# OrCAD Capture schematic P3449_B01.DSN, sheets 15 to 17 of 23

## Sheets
15 0008_USB3.1 x4 HUB: size Custom
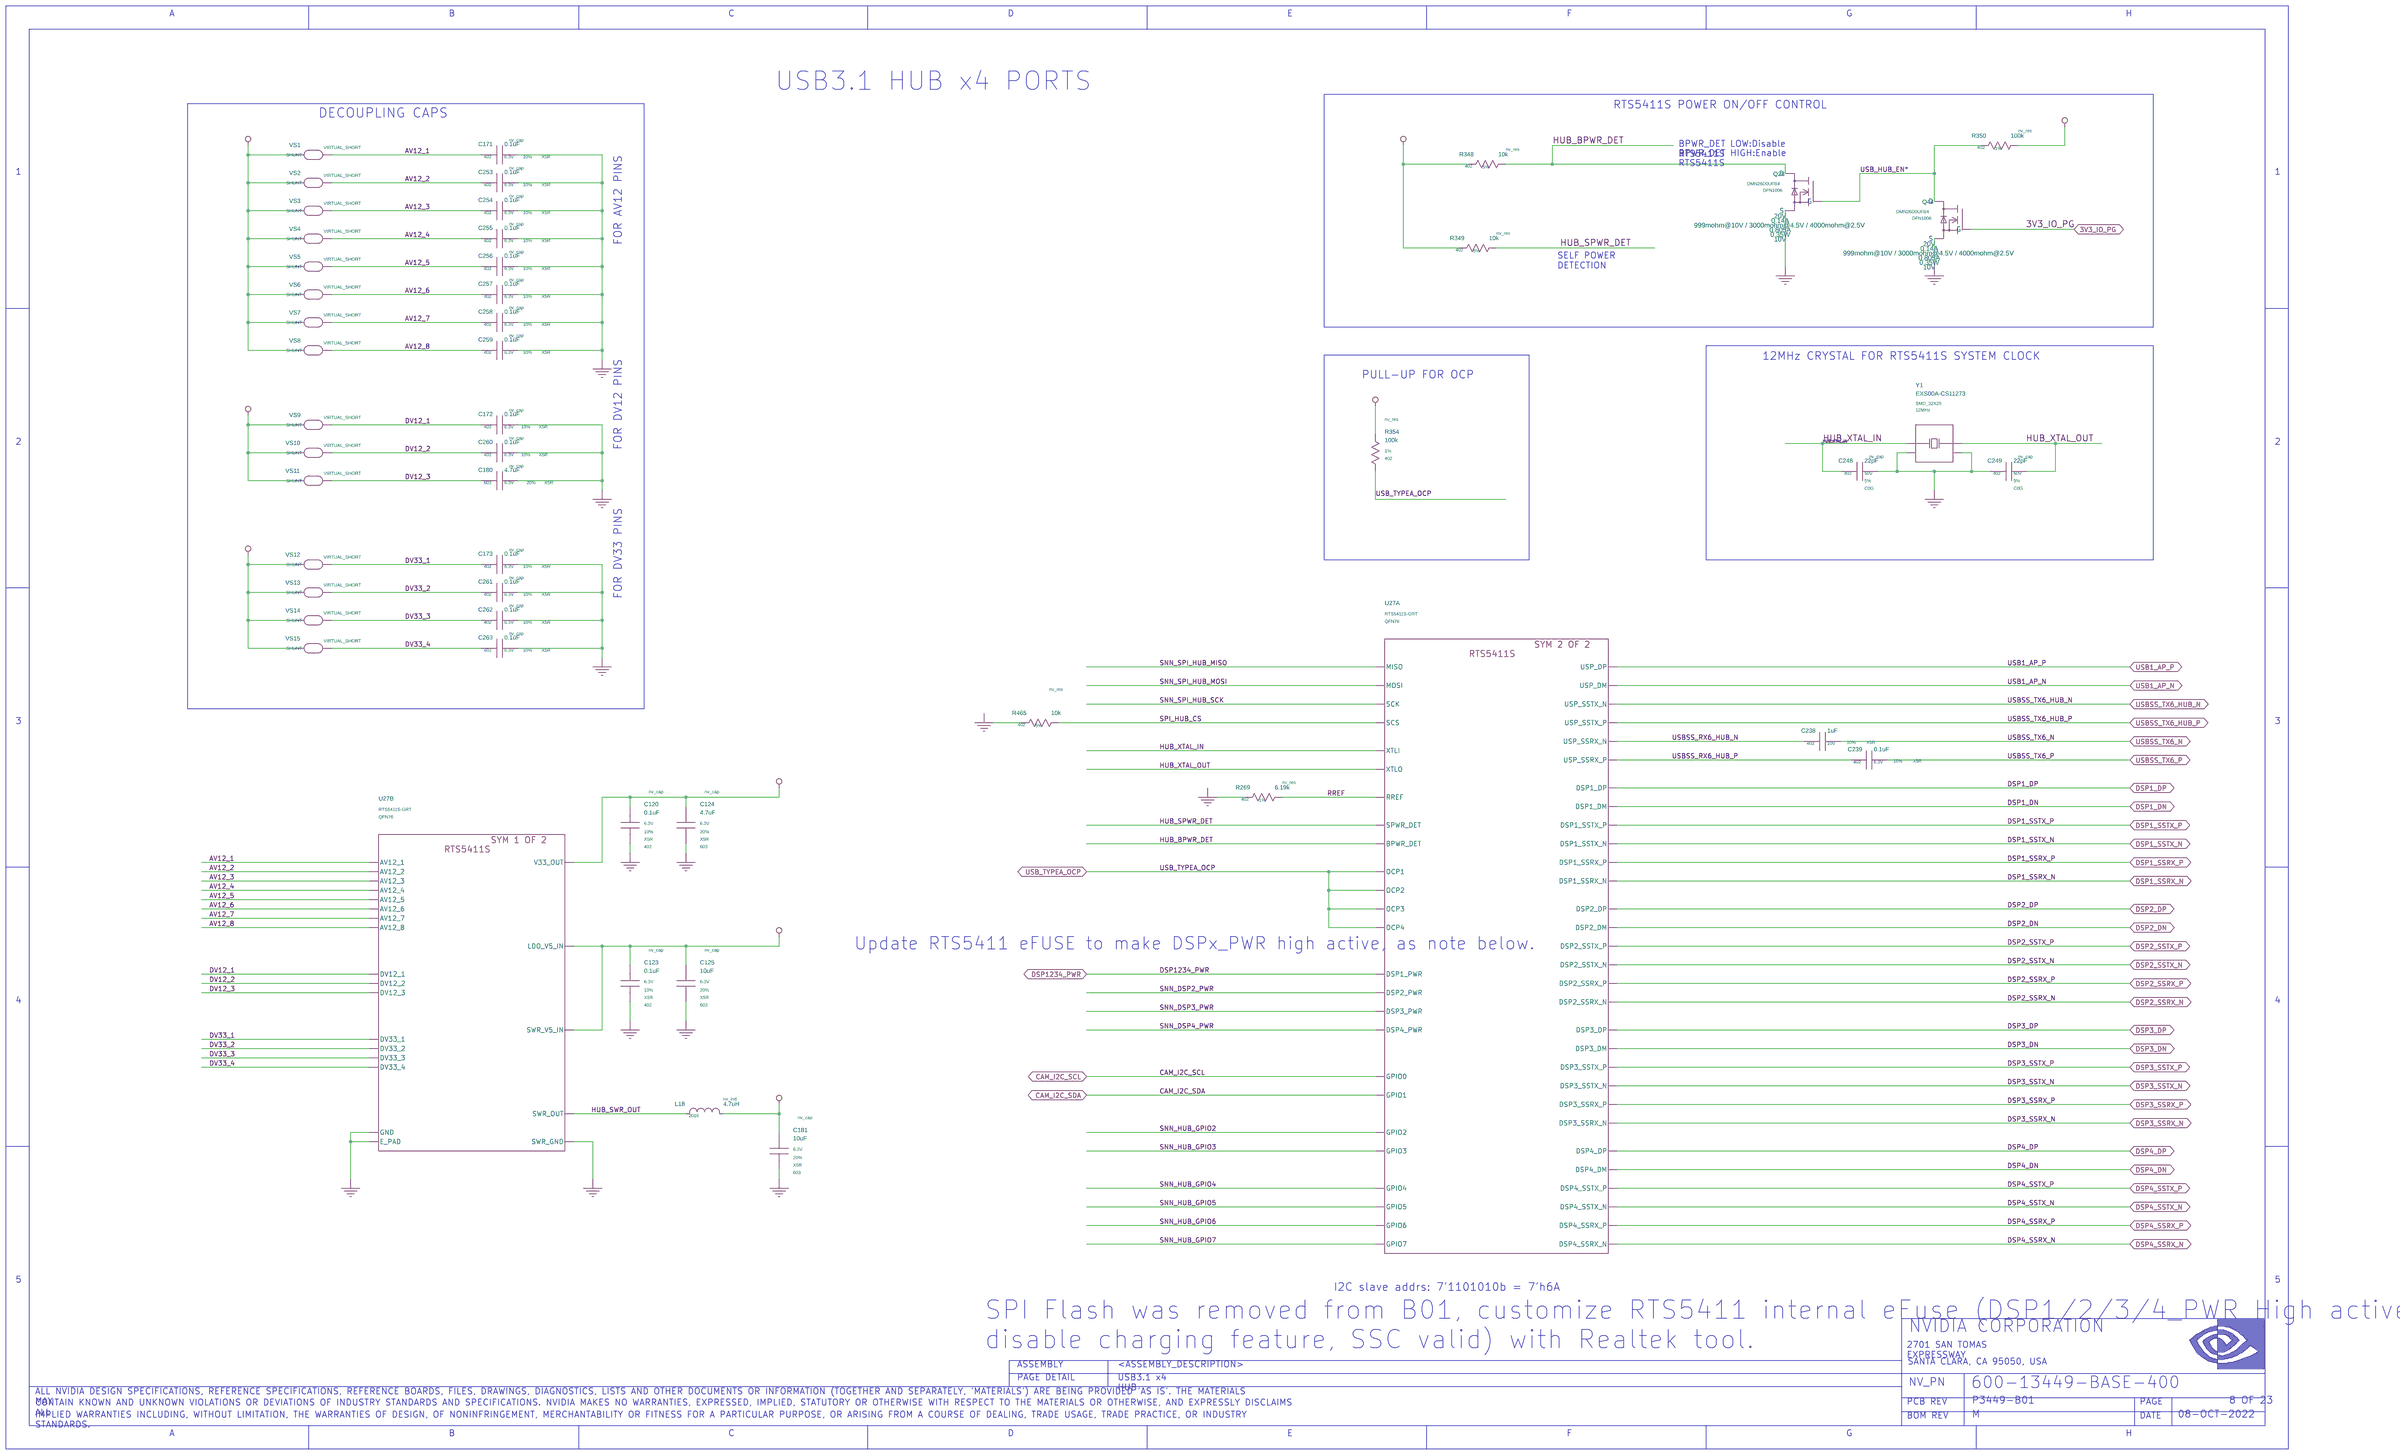
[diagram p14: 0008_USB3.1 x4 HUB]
16 0007_USB2.0 micro: size Custom
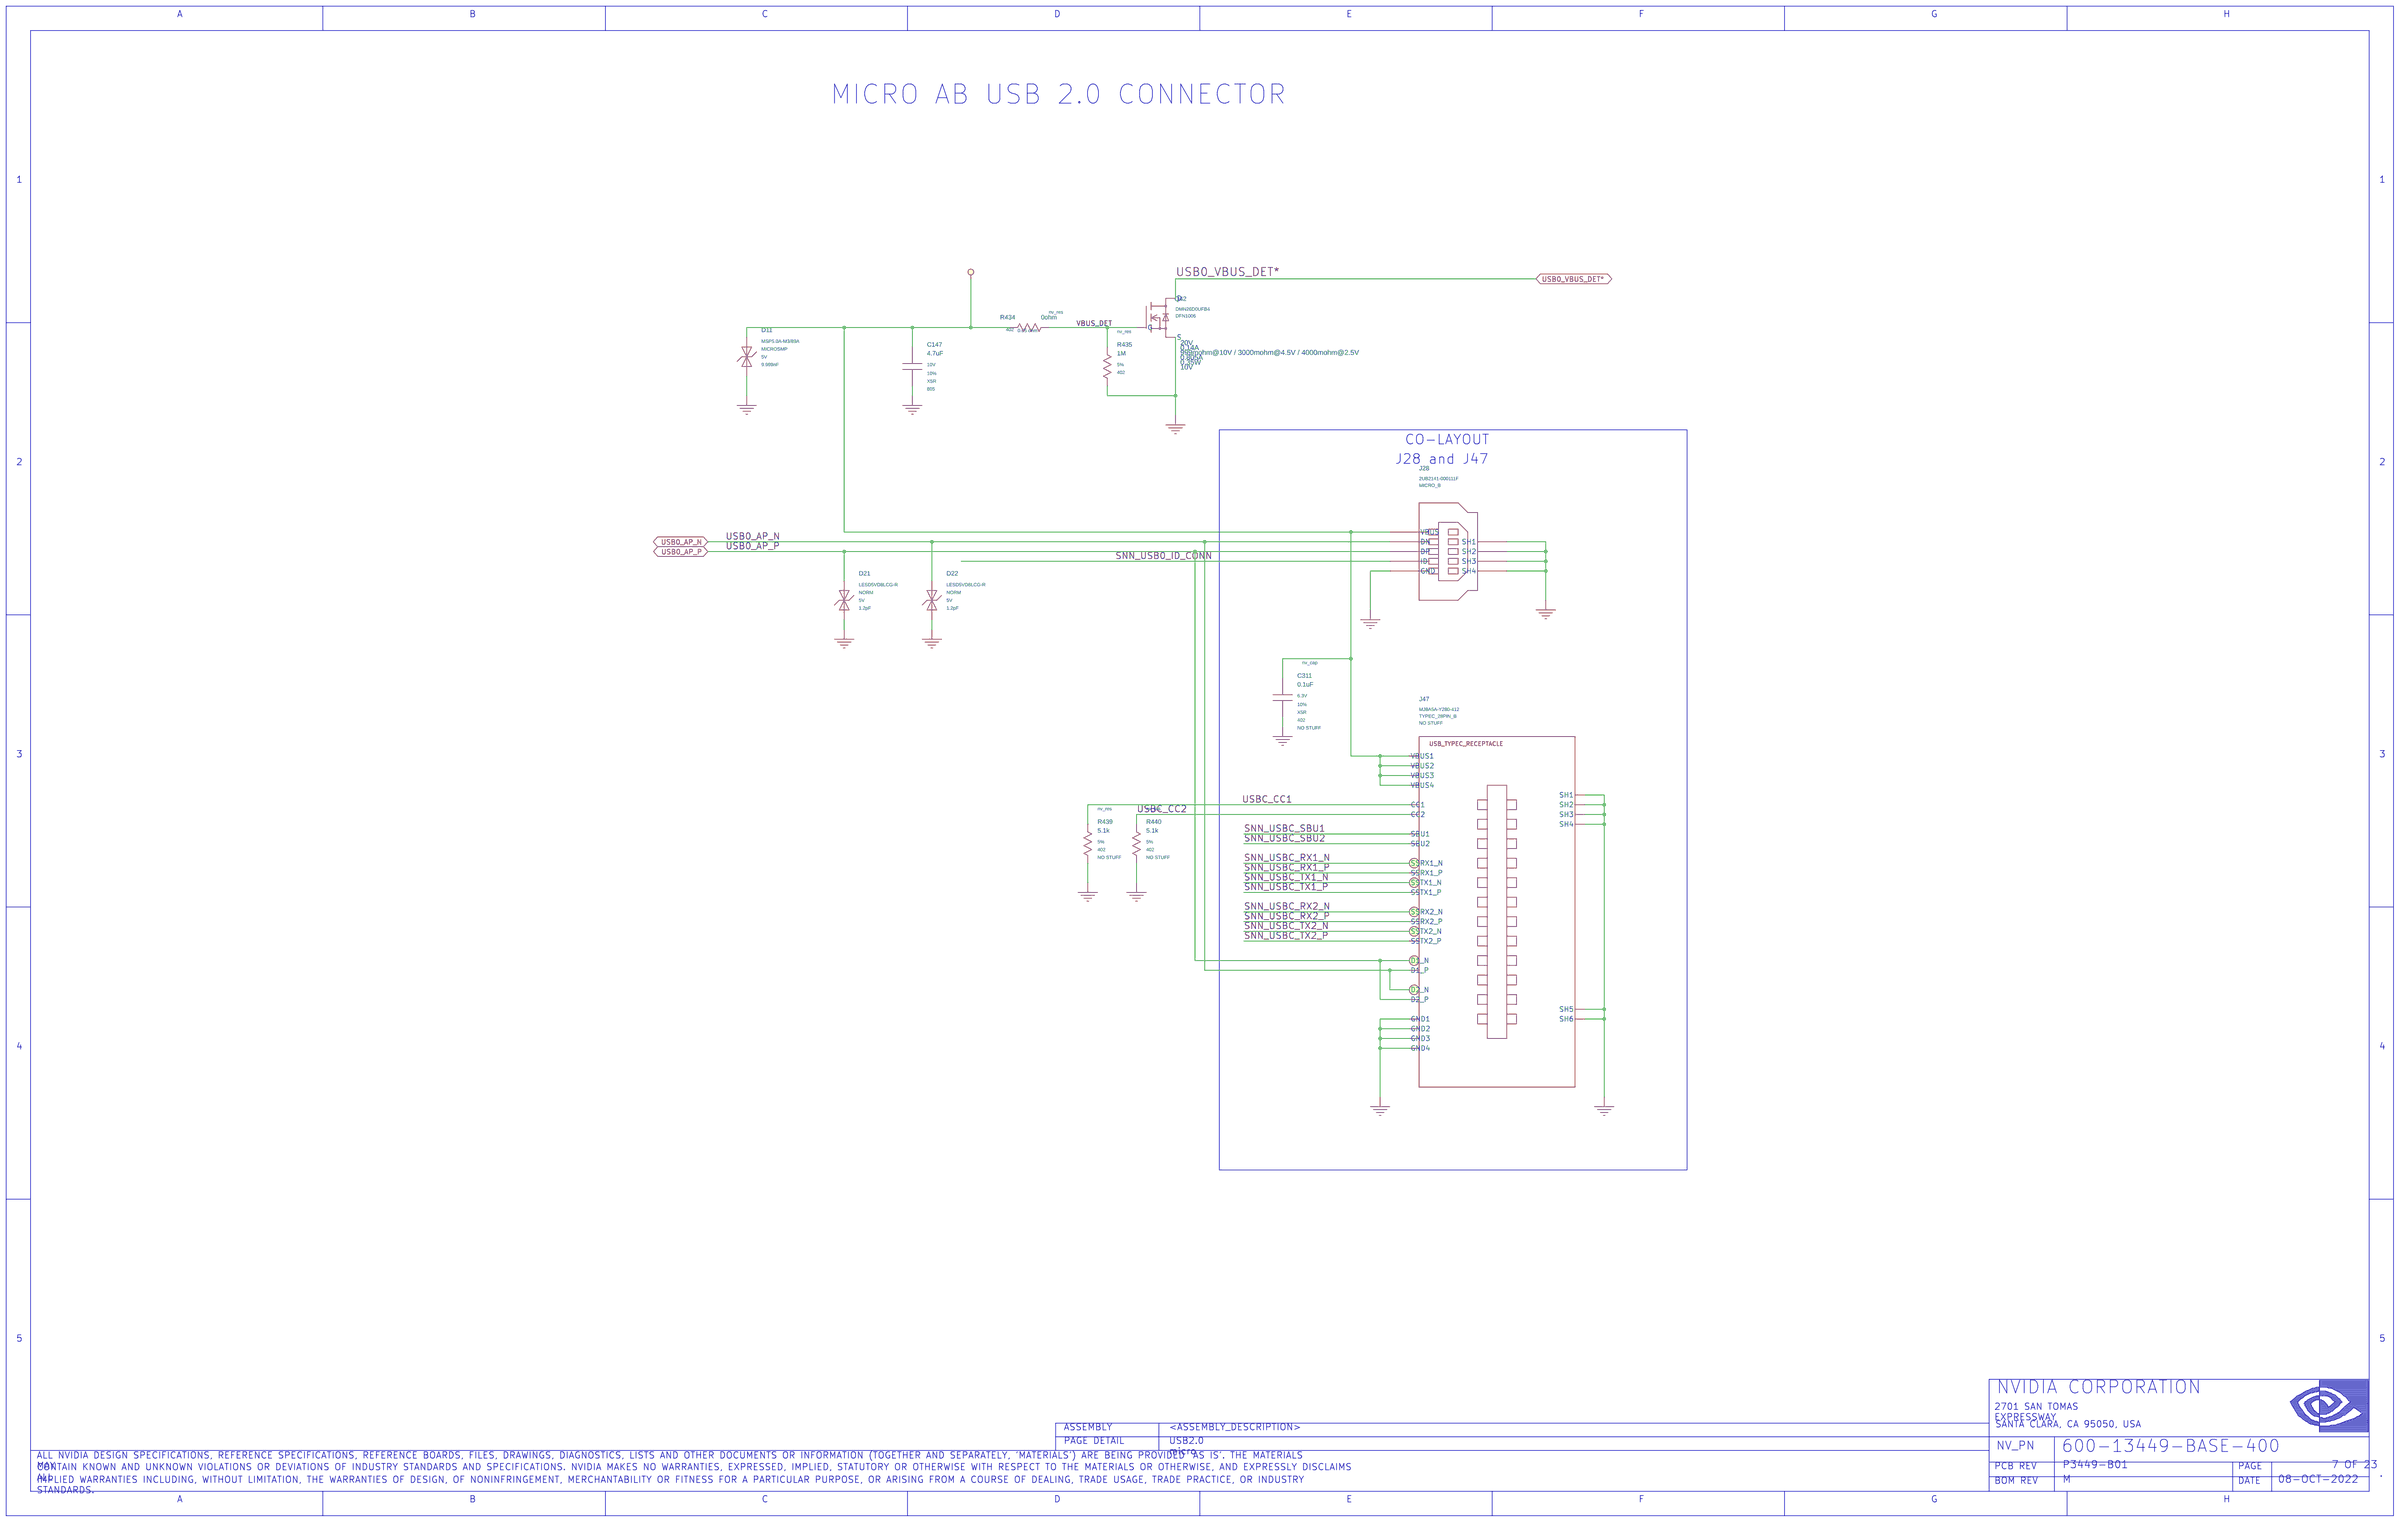
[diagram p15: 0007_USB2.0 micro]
17 0006_SODIMM connector 3_3: size Custom
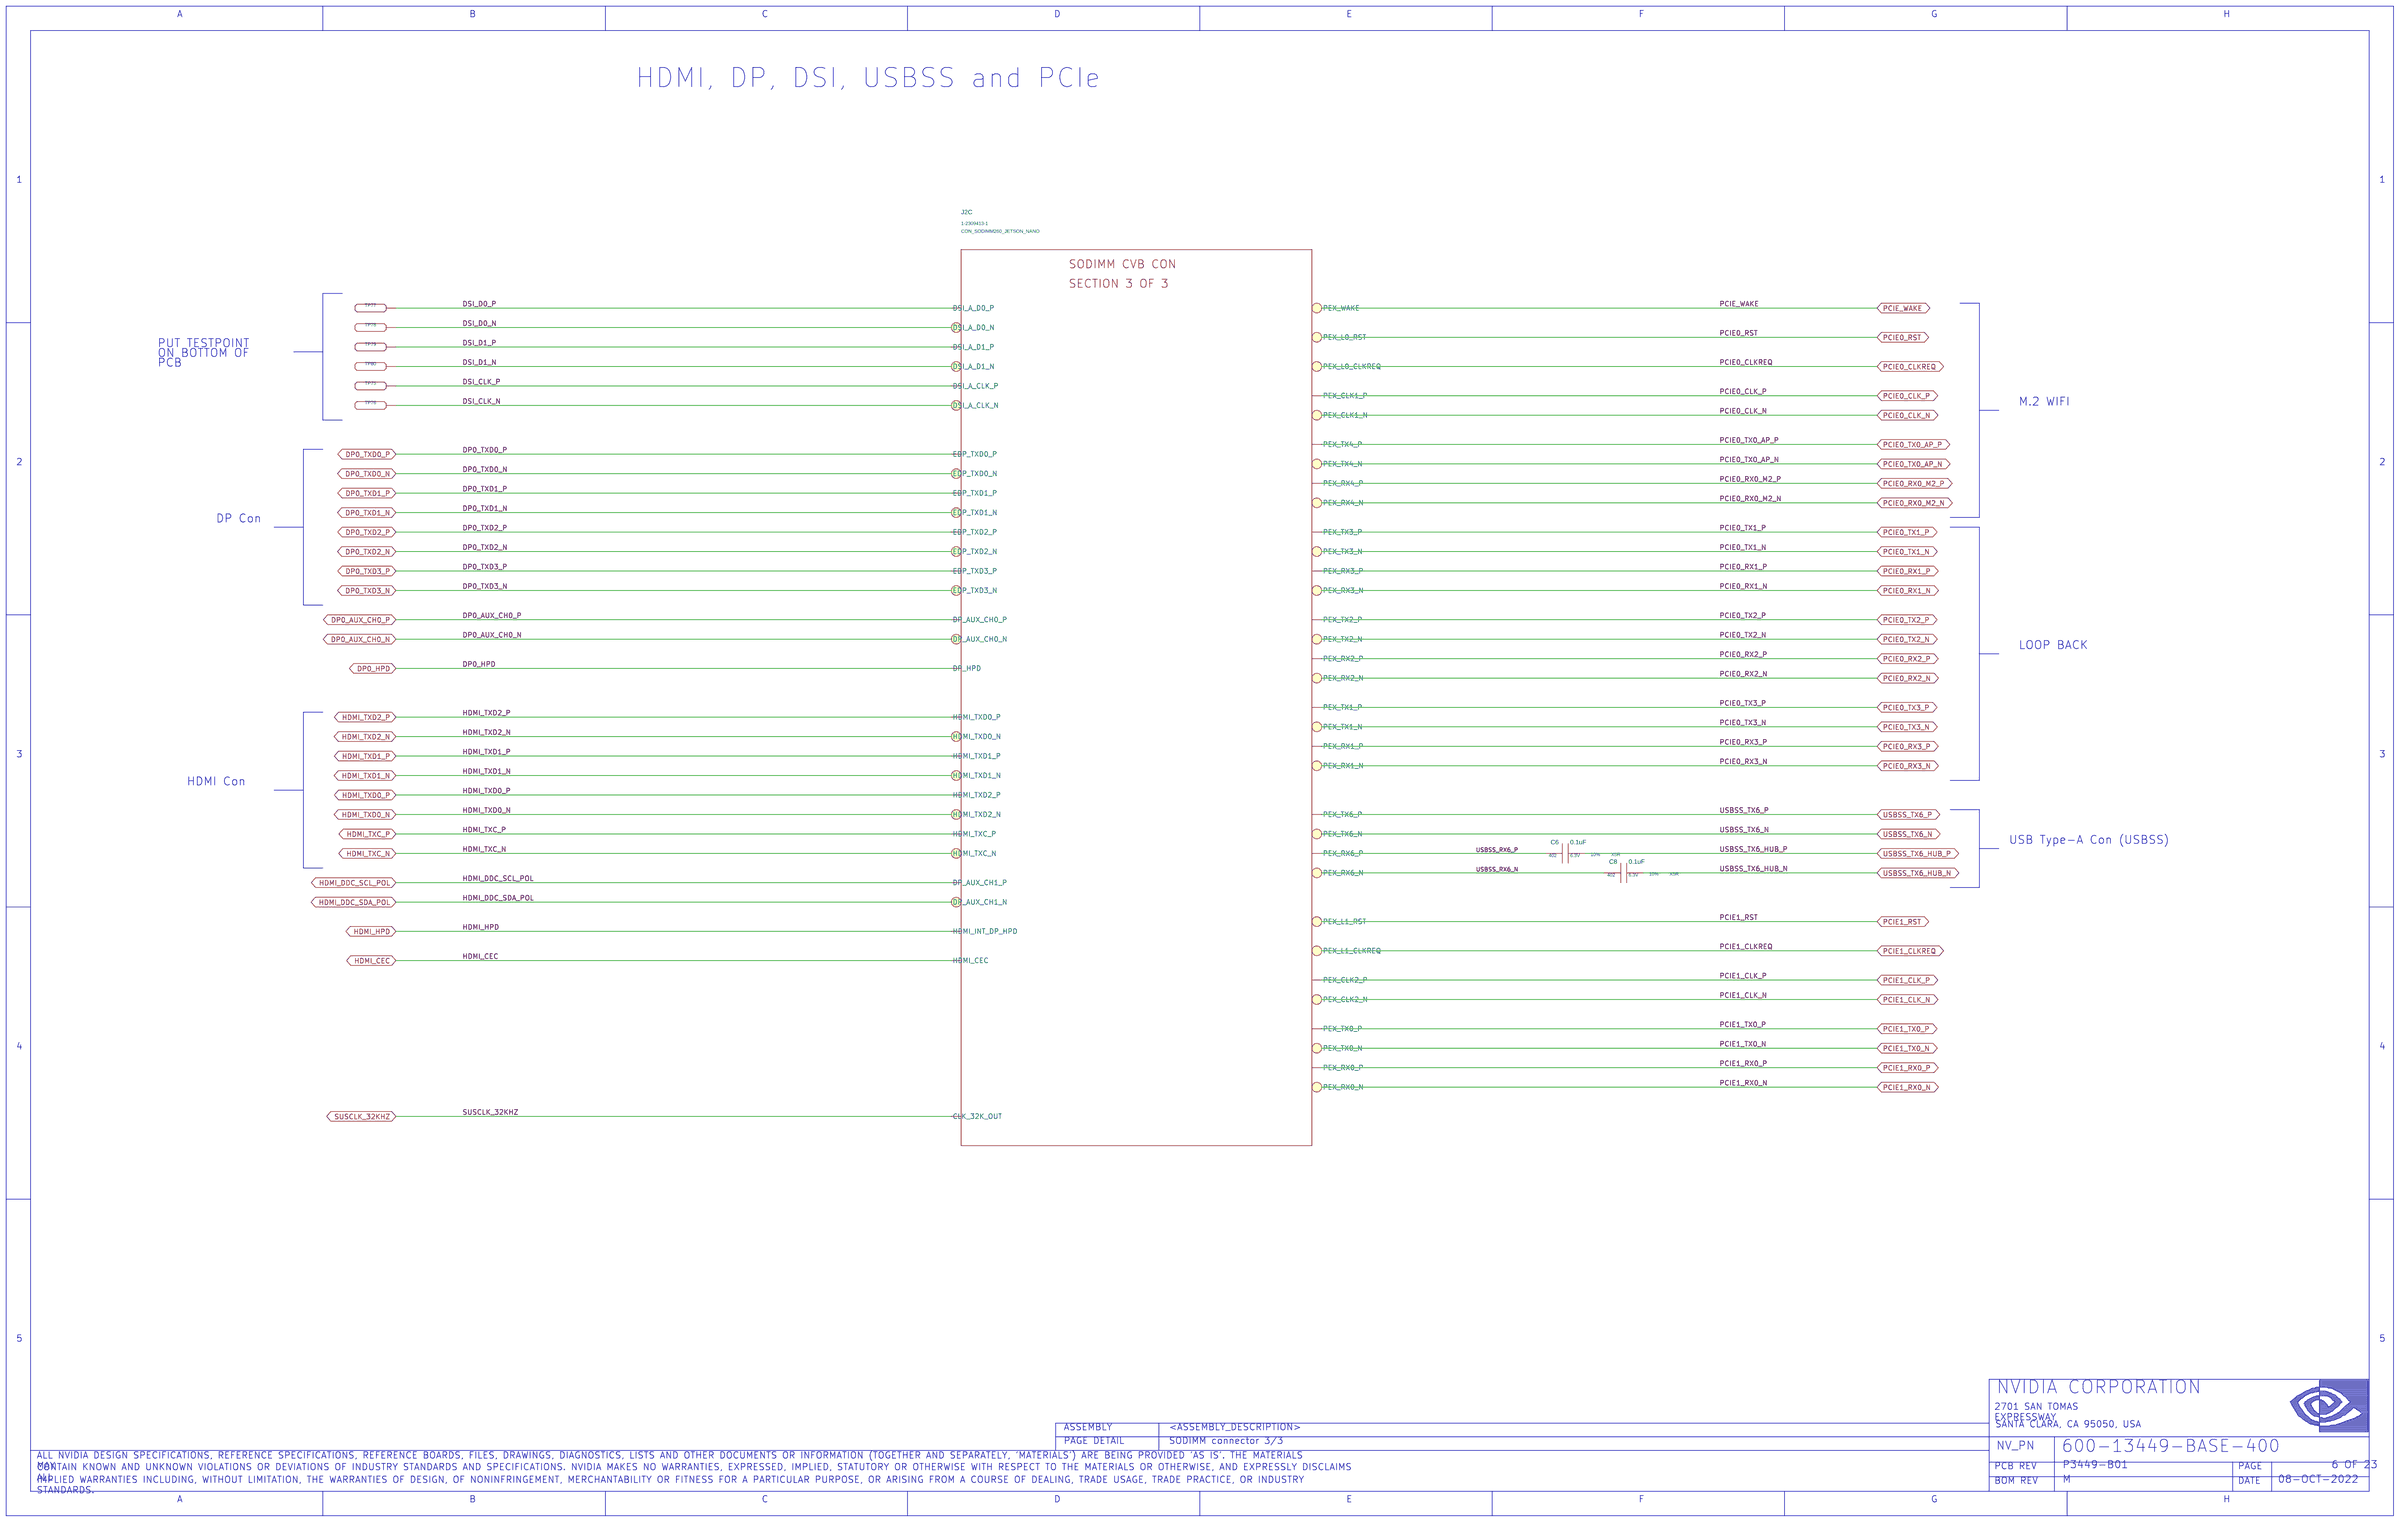
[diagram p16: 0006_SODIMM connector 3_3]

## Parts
sheet 0005_SODIMM connector 2_3
J2  CON_SODIMM_260  [CON_SODIMM_260_SMT_RA_F_P005]  (sections A,B,C)
sheet 0006_SODIMM connector 3_3
C6  0.1uF  [402]
C8  0.1uF  [402]
TP75  LABTESTPOINT  [LTPB071C125D045C025P]
TP76  LABTESTPOINT  [LTPB071C125D045C025P]
TP77  LABTESTPOINT  [LTPB071C125D045C025P]
TP78  LABTESTPOINT  [LTPB071C125D045C025P]
TP79  LABTESTPOINT  [LTPB071C125D045C025P]
TP80  LABTESTPOINT  [LTPB071C125D045C025P]
sheet 0007_USB2.0 micro
C147  4.7uF  [805]
C311  0.1uF  [402]
D11  D_ESD  [DIODE_SMD_025X013]
D21  D_ESD  [DIODE_SMD_010X060]
D22  D_ESD  [DIODE_SMD_010X060]
J28  CON_USB  [CON_USB_005_SMT_RA_080X066]
J47  CON_USB3  [CON_USB_024_SMT_RA_F_089X108]
Q42  Q_FET_N_ENH  [DFET_003_SMD_010X006_B]
R434  0ohm  [402]
R435  1M  [402]
R439  5.1k  [402]
R440  5.1k  [402]
sheet 0008_USB3.1 x4 HUB
C120  0.1uF  [402]
C123  0.1uF  [402]
C124  4.7uF  [603]
C125  10uF  [603]
C171  0.1uF  [402]
C172  0.1uF  [402]
C173  0.1uF  [402]
C180  4.7uF  [603]
C181  10uF  [603]
C238  1uF  [402]
C239  0.1uF  [402]
C248  22pF  [402]
C249  22pF  [402]
C253  0.1uF  [402]
C254  0.1uF  [402]
C255  0.1uF  [402]
C256  0.1uF  [402]
C257  0.1uF  [402]
C258  0.1uF  [402]
C259  0.1uF  [402]
C260  0.1uF  [402]
C261  0.1uF  [402]
C262  0.1uF  [402]
C263  0.1uF  [402]
L18  4.7uH  [2016MM]
Q28  Q_FET_N_ENH  [DFET_003_SMD_010X006_B]
Q44  Q_FET_N_ENH  [DFET_003_SMD_010X006_B]
R269  6.19k  [402]
R348  10k  [402]
R349  10k  [402]
R350  100k  [402]
R354  100k  [402]
R465  10k  [402]
U27  U_USB_HUB_RTS5411S  [QFN076Q_P040_0090_T054X054]  (sections A,B)
VS1  VIRTUAL_SHORT  [VIRTUAL_SHORT]
VS2  VIRTUAL_SHORT  [VIRTUAL_SHORT]
VS3  VIRTUAL_SHORT  [VIRTUAL_SHORT]
VS4  VIRTUAL_SHORT  [VIRTUAL_SHORT]
VS5  VIRTUAL_SHORT  [VIRTUAL_SHORT]
VS6  VIRTUAL_SHORT  [VIRTUAL_SHORT]
VS7  VIRTUAL_SHORT  [VIRTUAL_SHORT]
VS8  VIRTUAL_SHORT  [VIRTUAL_SHORT]
VS9  VIRTUAL_SHORT  [VIRTUAL_SHORT]
VS10  VIRTUAL_SHORT  [VIRTUAL_SHORT]
VS11  VIRTUAL_SHORT  [VIRTUAL_SHORT]
VS12  VIRTUAL_SHORT  [VIRTUAL_SHORT]
VS13  VIRTUAL_SHORT  [VIRTUAL_SHORT]
VS14  VIRTUAL_SHORT  [VIRTUAL_SHORT]
VS15  VIRTUAL_SHORT  [VIRTUAL_SHORT]
Y1  12MHz  [XTAL_SMD_4_032X025]

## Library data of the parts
J2 = CON_SODIMM_260: ANGLE: 90; ASSEMBLY: CVB_CONN; CDS_LIB: p3449_b01_lib; CDS_PART_NAME: CON_SODIMM_260_CON_SODIMM260_JETSON_NANO-2309413-1,FEMALE,0.5MM,90,[ ],[ ],YES,NO,NO,25 V,0.5 A,080-1656-000; CDS_PHYS_PART_NAME: CON_SODIMM_260_CON_SODIMM260_JETSON_NANO-2309413-1,FEMALE,0.5MM,90,[ ],[ ],YES,NO,NO,25 V,0.5 A,080-1656-000-080-1656-000; CDS_SEC: 1; CaptureCellPackProp: CON_SODIMM_260A; DEVICE_TYPENAME: CON_SODIMM_260_CON_SODIMM260_JETSON_NANO-2309413-1FEMALE05MM90YESNONO25V05A080-1656-000-080-1656-000; DRAWING: @P3449_B01_LIB.P3449_B01(SCH_1):PAGE4; EMI_GROUND_TAB: NO; GENDER: FEMALE; LATCHING: YES; MAX_CURRENT: 0.5 A; MAX_VOLTAGE: 25 V; NV_NAME: 1-2309413-1; NV_PN: 080-1656-000; PACK_TYPE: CON_SODIMM260_JETSON_NANO; PATH: I79; PHYS_PAGE: 4; PITCH: 0.5mm; REFLOW: [ ]; ROT: 0; SEC: 1; SEC_TYPE: CON_SODIMM260_JETSON_NANO; SHIELDED: NO; SHROUDED: [ ]; VER: 5; XY: (-9250,3800)
C6 = C: ASSEMBLY: CVB_CONN; CDS_LIB: discrete; CDS_PART_NAME: C_0402-0.1UF,X5R,10%,6.3V,039-0007-000; CDS_PHYS_PART_NAME: C_0402-0.1UF,X5R,10%,6.3V,039-0007-000-0.1UF,039-0007-000; CDS_SEC: 1; DEVICE_TYPENAME: C_0402-01UFX5R1063V039-0007-000-01UF039-0007-000; DRAWING: @P3449_B01_LIB.P3449_B01(SCH_1):PAGE6; MAT: X5R; MAX_VOLTAGE: 6.3V; NV_PN: 039-0007-000; PATH: I131; PHYS_PAGE: 6; ROT: 0; SEC: 1; SIGNAL_MODEL: nv_cap; TOL: 10%; VER: 2; XY: (-4150,3250)
C8 = C: ASSEMBLY: CVB_CONN; CDS_LIB: discrete; CDS_PART_NAME: C_0402-0.1UF,X5R,10%,6.3V,039-0007-000; CDS_PHYS_PART_NAME: C_0402-0.1UF,X5R,10%,6.3V,039-0007-000-0.1UF,039-0007-000; CDS_SEC: 1; DEVICE_TYPENAME: C_0402-01UFX5R1063V039-0007-000-01UF039-0007-000; DRAWING: @P3449_B01_LIB.P3449_B01(SCH_1):PAGE6; MAT: X5R; MAX_VOLTAGE: 6.3V; NV_PN: 039-0007-000; PATH: I128; PHYS_PAGE: 6; ROT: 0; SEC: 1; SIGNAL_MODEL: nv_cap; TOL: 10%; VER: 2; XY: (-3850,3150)
TP75 = LABTESTPOINT: CDS_LIB: electro_mechanic; CDS_PART_NAME: LABTESTPOINT_PIN-LTPB071C125; CDS_PHYS_PART_NAME: LABTESTPOINT_PIN-LTPB071C125; CDS_SEC: 1; DEVICE_TYPENAME: LABTESTPOINT_PIN-LTPB071C125; DRAWING: @P3449_B01_LIB.P3449_B01(SCH_1):PAGE6; NV_NAME: LTPB071C125; PACK_TYPE: PIN; PATH: I94; PHYS_PAGE: 6; ROT: 0; SEC: 1; VER: 1; XY: (-10200,5650)
TP76 = LABTESTPOINT: CDS_LIB: electro_mechanic; CDS_PART_NAME: LABTESTPOINT_PIN-LTPB071C125; CDS_PHYS_PART_NAME: LABTESTPOINT_PIN-LTPB071C125; CDS_SEC: 1; DEVICE_TYPENAME: LABTESTPOINT_PIN-LTPB071C125; DRAWING: @P3449_B01_LIB.P3449_B01(SCH_1):PAGE6; NV_NAME: LTPB071C125; PACK_TYPE: PIN; PATH: I91; PHYS_PAGE: 6; ROT: 0; SEC: 1; VER: 1; XY: (-10200,5550)
TP77 = LABTESTPOINT: CDS_LIB: electro_mechanic; CDS_PART_NAME: LABTESTPOINT_PIN-LTPB071C125; CDS_PHYS_PART_NAME: LABTESTPOINT_PIN-LTPB071C125; CDS_SEC: 1; DEVICE_TYPENAME: LABTESTPOINT_PIN-LTPB071C125; DRAWING: @P3449_B01_LIB.P3449_B01(SCH_1):PAGE6; NV_NAME: LTPB071C125; PACK_TYPE: PIN; PATH: I93; PHYS_PAGE: 6; ROT: 0; SEC: 1; VER: 1; XY: (-10200,6050)
TP78 = LABTESTPOINT: CDS_LIB: electro_mechanic; CDS_PART_NAME: LABTESTPOINT_PIN-LTPB071C125; CDS_PHYS_PART_NAME: LABTESTPOINT_PIN-LTPB071C125; CDS_SEC: 1; DEVICE_TYPENAME: LABTESTPOINT_PIN-LTPB071C125; DRAWING: @P3449_B01_LIB.P3449_B01(SCH_1):PAGE6; NV_NAME: LTPB071C125; PACK_TYPE: PIN; PATH: I90; PHYS_PAGE: 6; ROT: 0; SEC: 1; VER: 1; XY: (-10200,5950)
TP79 = LABTESTPOINT: CDS_LIB: electro_mechanic; CDS_PART_NAME: LABTESTPOINT_PIN-LTPB071C125; CDS_PHYS_PART_NAME: LABTESTPOINT_PIN-LTPB071C125; CDS_SEC: 1; DEVICE_TYPENAME: LABTESTPOINT_PIN-LTPB071C125; DRAWING: @P3449_B01_LIB.P3449_B01(SCH_1):PAGE6; NV_NAME: LTPB071C125; PACK_TYPE: PIN; PATH: I92; PHYS_PAGE: 6; ROT: 0; SEC: 1; VER: 1; XY: (-10200,5850)
TP80 = LABTESTPOINT: CDS_LIB: electro_mechanic; CDS_PART_NAME: LABTESTPOINT_PIN-LTPB071C125; CDS_PHYS_PART_NAME: LABTESTPOINT_PIN-LTPB071C125; CDS_SEC: 1; DEVICE_TYPENAME: LABTESTPOINT_PIN-LTPB071C125; DRAWING: @P3449_B01_LIB.P3449_B01(SCH_1):PAGE6; NV_NAME: LTPB071C125; PACK_TYPE: PIN; PATH: I89; PHYS_PAGE: 6; ROT: 0; SEC: 1; VER: 1; XY: (-10200,5750)
C147 = C#1: ASSEMBLY: MICRO_USB; CDS_LIB: discrete; CDS_PART_NAME: C_0805-4.7UF,X5R,10%,10V,039-0152-000; CDS_PHYS_PART_NAME: C_0805-4.7UF,X5R,10%,10V,039-0152-000-039-0152-000,4.7UF; CDS_SEC: 1; CHIPS_PART_NAME: C; DEVICE_TYPENAME: C_0805-47UFX5R1010V039-0152-000-039-0152-00047UF; DRAWING: @P3449_B01_LIB.P3449_B01(SCH_1):PAGE7; MAT: X5R; MAX_VOLTAGE: 10V; NV_PN: 039-0152-000; PATH: I7; PHYS_PAGE: 7; ROT: 0; SEC: 1; SIGNAL_MODEL: nv_cap; TOL: 10%; VER: 1; XY: (-7500,5750)
C311 = C#1: ASSEMBLY: USBC_PWR; CDS_LIB: discrete; CDS_PART_NAME: C_0402-0.1UF,X5R,10%,6.3V,039-0007-000; CDS_PHYS_PART_NAME: C_0402-0.1UF,X5R,10%,6.3V,039-0007-000-0.1UF,039-0007-000; CDS_SEC: 1; CHIPS_PART_NAME: C; DEVICE_TYPENAME: C_0402-01UFX5R1063V039-0007-000-01UF039-0007-000; DRAWING: @P3449_B01_LIB.P3449_B01(SCH_1):PAGE7; MAT: X5R; MAX_VOLTAGE: 6.3V; NV_PN: 039-0007-000; PATH: I58; PHYS_PAGE: 7; ROT: 0; SEC: 1; SIGNAL_MODEL: nv_cap; SKU: NO STUFF; TOL: 10%; VER: 1; XY: (-5600,4050)
D11 = D_ESD: ASSEMBLY: MICRO_USB; BREAKDOWN_VOLTAGE_MIN_TYP: 6.4V; CAPACITANCE_MAX_TYP: 9.999nF; CDS_LIB: discrete; CDS_PART_NAME: D_ESD_MICROSMP-MSP5.0A-M3/89A,1 LINE,UNI-DIRECTIONAL,5V,100UA,6.4V,9.2V@16.3A,9.999NF,090-0233-000; CDS_PHYS_PART_NAME: D_ESD_MICROSMP-MSP5.0A-M3/89A,1 LINE,UNI-DIRECTIONAL,5V,100UA,6.4V,9.2V@16.3A,9.999NF,090-0233-000-090-0233-000; CDS_SEC: 1; CLAMPING_VOLTAGE: 9.2V@16.3A; CONFIGURATION: 1 Line; DEVICE_TYPENAME: D_ESD_MICROSMP-MSP50A-M389A1LINEUNI-DIRECTIONAL5V100UA64V92V163A9999NF090-0233-000-090-0233-000; DRAWING: @P3449_B01_LIB.P3449_B01(SCH_1):PAGE7; MAX_REVERSE_LEAKAGE_CURRENT: 100uA; MAX_REVERSE_VOLTAGE: 5V; NV_NAME: MSP5.0A-M3/89A; NV_PN: 090-0233-000; PACK_TYPE: MICROSMP; PATH: I13; PHYS_PAGE: 7; POLARITY: Uni-Directional; ROT: 0; SEC: 1; SEC_TYPE: MICROSMP; VER: 2; XY: (-8350,5800)
D21 = D_ESD: ASSEMBLY: MICRO_USB; BREAKDOWN_VOLTAGE_MIN_TYP: 5.5V; CAPACITANCE_MAX_TYP: 1.2pF; CDS_LIB: discrete; CDS_PART_NAME: D_ESD_NORM-LESD5VD8LCG-R,1 LINE,BI-DIRECTIONAL,5V,0.05UA,5.5V,10V@2A,1.2PF,090-0172-000; CDS_PHYS_PART_NAME: D_ESD_NORM-LESD5VD8LCG-R,1 LINE,BI-DIRECTIONAL,5V,0.05UA,5.5V,10V@2A,1.2PF,090-0172-000-090-0172-000; CDS_SEC: 1; CLAMPING_VOLTAGE: 10V@2A; CONFIGURATION: 1 Line; DEVICE_TYPENAME: D_ESD_NORM-LESD5VD8LCG-R1LINEBI-DIRECTIONAL5V005UA55V10V2A12PF090-0172-000-090-0172-000; DRAWING: @P3449_B01_LIB.P3449_B01(SCH_1):PAGE7; MAX_REVERSE_LEAKAGE_CURRENT: 0.05uA; MAX_REVERSE_VOLTAGE: 5V; NV_NAME: LESD5VD8LCG-R; NV_PN: 090-0172-000; PACK_TYPE: NORM; PATH: I43; PHYS_PAGE: 7; POLARITY: Bi-Directional; ROT: 0; SEC: 1; VER: 2; XY: (-7850,4550)
D22 = D_ESD: ASSEMBLY: MICRO_USB; BREAKDOWN_VOLTAGE_MIN_TYP: 5.5V; CAPACITANCE_MAX_TYP: 1.2pF; CDS_LIB: discrete; CDS_PART_NAME: D_ESD_NORM-LESD5VD8LCG-R,1 LINE,BI-DIRECTIONAL,5V,0.05UA,5.5V,10V@2A,1.2PF,090-0172-000; CDS_PHYS_PART_NAME: D_ESD_NORM-LESD5VD8LCG-R,1 LINE,BI-DIRECTIONAL,5V,0.05UA,5.5V,10V@2A,1.2PF,090-0172-000-090-0172-000; CDS_SEC: 1; CLAMPING_VOLTAGE: 10V@2A; CONFIGURATION: 1 Line; DEVICE_TYPENAME: D_ESD_NORM-LESD5VD8LCG-R1LINEBI-DIRECTIONAL5V005UA55V10V2A12PF090-0172-000-090-0172-000; DRAWING: @P3449_B01_LIB.P3449_B01(SCH_1):PAGE7; MAX_REVERSE_LEAKAGE_CURRENT: 0.05uA; MAX_REVERSE_VOLTAGE: 5V; NV_NAME: LESD5VD8LCG-R; NV_PN: 090-0172-000; PACK_TYPE: NORM; PATH: I44; PHYS_PAGE: 7; POLARITY: Bi-Directional; ROT: 0; SEC: 1; VER: 2; XY: (-7400,4550)
J28 = CON_USB: ANGLE: 90; ASSEMBLY: MICRO_USB; CDS_LIB: electro_mechanic; CDS_PART_NAME: CON_USB_MICRO_B-2UB2141-000111F,FEMALE,0.65,90,YES,YES,YES,NO,YES,500.0 V,500.0 MA,080-1368-000; CDS_PHYS_PART_NAME: CON_USB_MICRO_B-2UB2141-000111F,FEMALE,0.65,90,YES,YES,YES,NO,YES,500.0 V,500.0 MA,080-1368-000-080-1368-000; CDS_SEC: 1; DEVICE_TYPENAME: CON_USB_MICRO_B-2UB2141-000111FFEMALE06590YESYESYESNOYES5000V5000MA080-1368-000-080-1368-000; DRAWING: @P3449_B01_LIB.P3449_B01(SCH_1):PAGE7; EMI_GROUND_TAB: NO; GENDER: FEMALE; LATCHING: YES; MAX_CURRENT: 500.0 mA; MAX_VOLTAGE: 500.0 V; NV_NAME: 2UB2141-000111F; NV_PN: 080-1368-000; PACK_TYPE: MICRO_B; PATH: I12; PHYS_PAGE: 7; PITCH: 0.65; PLACEMENT_NOTE: COLAYOUT WITH J47; REFLOW: YES; ROT: 0; SEC: 1; SEC_TYPE: MICRO_B; SHIELDED: YES; SHROUDED: YES; VER: 2; XY: (-4750,4800)
J47 = CON_USB3: ANGLE: 90; ASSEMBLY: USBC_PWR; CDS_LIB: electro_mechanic; CDS_PART_NAME: CON_USB3_TYPEC_28PIN_B-MJ8A5A-Y280-412,RECEPTACLE,0.5MM,90,YES,YES,YES,NO,YES,100 V,0.25 A,064-0305-000; CDS_PHYS_PART_NAME: CON_USB3_TYPEC_28PIN_B-MJ8A5A-Y280-412,RECEPTACLE,0.5MM,90,YES,YES,YES,NO,YES,100 V,0.25 A,064-0305-000-064-0305-000; CDS_SEC: 1; DEVICE_TYPENAME: CON_USB3_TYPEC_28PIN_B-MJ8A5A-Y280-412RECEPTACLE05MM90YESYESYESNOYES100V025A064-0305-000-064-0305-000; DRAWING: @P3449_B01_LIB.P3449_B01(SCH_1):PAGE7; EMI_GROUND_TAB: NO; GENDER: RECEPTACLE; LATCHING: YES; MAX_CURRENT: 0.25 A; MAX_VOLTAGE: 100 V; NV_NAME: MJ8A5A-Y280-412; NV_PN: 064-0305-000; PACK_TYPE: TYPEC_28PIN_B; PATH: I51; PHYS_PAGE: 7; PITCH: 0.5mm; PLACEMENT_NOTE: COLAYOUT WITH J28; REFLOW: YES; ROT: 0; SEC: 1; SHIELDED: YES; SHROUDED: YES; SKU: NO STUFF; VER: 10; XY: (-4500,2950)
Q42 = Q_FET_N_ENH#1: ASSEMBLY: MICRO_USB; CDS_LIB: discrete; CDS_PART_NAME: Q_FET_N_ENH_DFN1006-DMN26D0UFB4,20V,999MOHM@10V / 3000MOHM@4.5V / 4000MOHM@2.5V,0.14A,0.805A,10V,0.35W,999NC@10V / 0NC@4.5V / A; CDS_PHYS_PART_NAME: Q_FET_N_ENH_DFN1006-DMN26D0UFB4,20V,999MOHM@10V / 3000MOHM@4.5V / 4000MOHM@2.5V,0.14A,0.805A,10V,0.35W,999NC@10V / 0NC@4.5V / B; CDS_SEC: 1; CONTINUOUS_CURRENT: 0.14A; CaptureCellPackProp: Q_FET_N_ENH##1; DEVICE_TYPENAME: Q_FET_N_ENH_DFN1006-DMN26D0UFB420V999MOHM10V3000MOHM45V4000MOHM25V014A0805A10V035W999NC10V0NC45VB; DRAWING: @P3449_B01_LIB.P3449_B01(SCH_1):PAGE7; MAX_CURRENT: 0.805A; MAX_VOLTAGE: 20V; MAX_WATTAGE: 0.35W; NV_NAME: DMN26D0UFB4; NV_PN: 300-0868-000; PACK_TYPE: DFN1006; PATH: I46; PHYS_PAGE: 7; Q_G: 999nC@10V / 0nC@4.5V / 999nC@2.5V; ROT: 0; R_DS_ON: 999mohm@10V / 3000mohm@4.5V / 4000mohm@2.5V; SEC: 1; VER: 2; V_BE_GS: 10V; XY: (-6250,6000)
R434 = R#1: ASSEMBLY: MICRO_USB; CDS_LIB: discrete; CDS_PART_NAME: R_0402-0OHM,0.05 OHM,62.5MW,195-2655-000; CDS_PHYS_PART_NAME: R_0402-0OHM,0.05 OHM,62.5MW,195-2655-000-0OHM,195-2655-000; CDS_SEC: 1; CHIPS_PART_NAME: R; DEVICE_TYPENAME: R_0402-0OHM005OHM625MW195-2655-000-0OHM195-2655-000; DRAWING: @P3449_B01_LIB.P3449_B01(SCH_1):PAGE7; MAX_WATTAGE: 62.5mW; NV_PN: 195-2655-000; PATH: I47; PHYS_PAGE: 7; ROT: 0; SEC: 1; SIGNAL_MODEL: nv_res; TOL: 0.05 ohm; VER: 1; XY: (-6900,5950)
R435 = R: ASSEMBLY: MICRO_USB; CDS_LIB: discrete; CDS_PART_NAME: R_0402-1M,5 %,62.5MW,195-0488-000; CDS_PHYS_PART_NAME: R_0402-1M,5 %,62.5MW,195-0488-000-195-0488-000,1M; CDS_SEC: 1; DEVICE_TYPENAME: R_0402-1M5625MW195-0488-000-195-0488-0001M; DRAWING: @P3449_B01_LIB.P3449_B01(SCH_1):PAGE7; MAX_WATTAGE: 62.5mW; NV_PN: 195-0488-000; PATH: I48; PHYS_PAGE: 7; ROT: 0; SEC: 1; SIGNAL_MODEL: nv_res; TOL: 5%; VER: 2; XY: (-6500,5750)
R439 = R: ASSEMBLY: USBC_PWR; CDS_LIB: discrete; CDS_PART_NAME: R_0402-5.1K,5 %,62.5MW,195-0605-000; CDS_PHYS_PART_NAME: R_0402-5.1K,5 %,62.5MW,195-0605-000-195-0605-000,5.1K; CDS_SEC: 1; DEVICE_TYPENAME: R_0402-51K5625MW195-0605-000-195-0605-00051K; DRAWING: @P3449_B01_LIB.P3449_B01(SCH_1):PAGE7; MAX_WATTAGE: 62.5mW; NV_PN: 195-0605-000; PATH: I53; PHYS_PAGE: 7; ROT: 0; SEC: 1; SIGNAL_MODEL: nv_res; SKU: NO STUFF; TOL: 5%; VER: 2; XY: (-6600,3300)
R440 = R: ASSEMBLY: USBC_PWR; CDS_LIB: discrete; CDS_PART_NAME: R_0402-5.1K,5 %,62.5MW,195-0605-000; CDS_PHYS_PART_NAME: R_0402-5.1K,5 %,62.5MW,195-0605-000-195-0605-000,5.1K; CDS_SEC: 1; DEVICE_TYPENAME: R_0402-51K5625MW195-0605-000-195-0605-00051K; DRAWING: @P3449_B01_LIB.P3449_B01(SCH_1):PAGE7; MAX_WATTAGE: 62.5mW; NV_PN: 195-0605-000; PATH: I54; PHYS_PAGE: 7; ROT: 0; SEC: 1; SIGNAL_MODEL: nv_res; SKU: NO STUFF; TOL: 5%; VER: 2; XY: (-6350,3300)
C120 = C#1: ASSEMBLY: USB3_TYPEA; CDS_LIB: discrete; CDS_PART_NAME: C_0402-0.1UF,X5R,10%,6.3V,039-0007-000; CDS_PHYS_PART_NAME: C_0402-0.1UF,X5R,10%,6.3V,039-0007-000-0.1UF,039-0007-000; CDS_SEC: 1; CHIPS_PART_NAME: C; DEVICE_TYPENAME: C_0402-01UFX5R1063V039-0007-000-01UF039-0007-000; DRAWING: @P3449_B01_LIB.P3449_B01(SCH_1):PAGE8; MAT: X5R; MAX_VOLTAGE: 6.3V; NV_PN: 039-0007-000; PATH: I5; PHYS_PAGE: 8; ROT: 0; SEC: 1; SIGNAL_MODEL: nv_cap; TOL: 10%; VER: 1; XY: (-8800,3200)
C123 = C#1: ASSEMBLY: USB3_TYPEA; CDS_LIB: discrete; CDS_PART_NAME: C_0402-0.1UF,X5R,10%,6.3V,039-0007-000; CDS_PHYS_PART_NAME: C_0402-0.1UF,X5R,10%,6.3V,039-0007-000-0.1UF,039-0007-000; CDS_SEC: 1; CHIPS_PART_NAME: C; DEVICE_TYPENAME: C_0402-01UFX5R1063V039-0007-000-01UF039-0007-000; DRAWING: @P3449_B01_LIB.P3449_B01(SCH_1):PAGE8; MAT: X5R; MAX_VOLTAGE: 6.3V; NV_PN: 039-0007-000; PATH: I11; PHYS_PAGE: 8; ROT: 0; SEC: 1; SIGNAL_MODEL: nv_cap; TOL: 10%; VER: 1; XY: (-8800,2350)
C124 = C#1: ASSEMBLY: USB3_TYPEA; CDS_LIB: discrete; CDS_PART_NAME: C_0603-4.7UF,X5R,20%,6.3V,032-0886-000; CDS_PHYS_PART_NAME: C_0603-4.7UF,X5R,20%,6.3V,032-0886-000-032-0886-000,4.7UF; CDS_SEC: 1; CHIPS_PART_NAME: C; DEVICE_TYPENAME: C_0603-47UFX5R2063V032-0886-000-032-0886-00047UF; DRAWING: @P3449_B01_LIB.P3449_B01(SCH_1):PAGE8; MAT: X5R; MAX_VOLTAGE: 6.3V; NV_PN: 032-0886-000; PATH: I6; PHYS_PAGE: 8; ROT: 0; SEC: 1; SIGNAL_MODEL: nv_cap; TOL: 20%; VER: 1; XY: (-8500,3200)
C125 = C#1: ASSEMBLY: USB3_TYPEA; CDS_LIB: discrete; CDS_PART_NAME: C_0603-10UF,X5R,20%,6.3V,039-0135-000; CDS_PHYS_PART_NAME: C_0603-10UF,X5R,20%,6.3V,039-0135-000-039-0135-000,10UF; CDS_SEC: 1; CHIPS_PART_NAME: C; DEVICE_TYPENAME: C_0603-10UFX5R2063V039-0135-000-039-0135-00010UF; DRAWING: @P3449_B01_LIB.P3449_B01(SCH_1):PAGE8; MAT: X5R; MAX_VOLTAGE: 6.3V; NV_PN: 039-0135-000; PATH: I9; PHYS_PAGE: 8; ROT: 0; SEC: 1; SIGNAL_MODEL: nv_cap; TOL: 20%; VER: 1; XY: (-8500,2350)
C171 = C: ASSEMBLY: USB3_TYPEA; CDS_LIB: discrete; CDS_PART_NAME: C_0402-0.1UF,X5R,10%,6.3V,039-0007-000; CDS_PHYS_PART_NAME: C_0402-0.1UF,X5R,10%,6.3V,039-0007-000-0.1UF,039-0007-000; CDS_SEC: 1; DEVICE_TYPENAME: C_0402-01UFX5R1063V039-0007-000-01UF039-0007-000; DRAWING: @P3449_B01_LIB.P3449_B01(SCH_1):PAGE8; MAT: X5R; MAX_VOLTAGE: 6.3V; NV_PN: 039-0007-000; PATH: I17; PHYS_PAGE: 8; ROT: 0; SEC: 1; SIGNAL_MODEL: nv_cap; TOL: 10%; VER: 2; XY: (-9500,6800)
C172 = C: ASSEMBLY: USB3_TYPEA; CDS_LIB: discrete; CDS_PART_NAME: C_0402-0.1UF,X5R,10%,6.3V,039-0007-000; CDS_PHYS_PART_NAME: C_0402-0.1UF,X5R,10%,6.3V,039-0007-000-0.1UF,039-0007-000; CDS_SEC: 1; DEVICE_TYPENAME: C_0402-01UFX5R1063V039-0007-000-01UF039-0007-000; DRAWING: @P3449_B01_LIB.P3449_B01(SCH_1):PAGE8; MAT: X5R; MAX_VOLTAGE: 6.3V; NV_PN: 039-0007-000; PATH: I21; PHYS_PAGE: 8; ROT: 0; SEC: 1; SIGNAL_MODEL: nv_cap; TOL: 10%; VER: 2; XY: (-9500,5350)
C173 = C: ASSEMBLY: USB3_TYPEA; CDS_LIB: discrete; CDS_PART_NAME: C_0402-0.1UF,X5R,10%,6.3V,039-0007-000; CDS_PHYS_PART_NAME: C_0402-0.1UF,X5R,10%,6.3V,039-0007-000-0.1UF,039-0007-000; CDS_SEC: 1; DEVICE_TYPENAME: C_0402-01UFX5R1063V039-0007-000-01UF039-0007-000; DRAWING: @P3449_B01_LIB.P3449_B01(SCH_1):PAGE8; MAT: X5R; MAX_VOLTAGE: 6.3V; NV_PN: 039-0007-000; PATH: I121; PHYS_PAGE: 8; ROT: 0; SEC: 1; SIGNAL_MODEL: nv_cap; TOL: 10%; VER: 2; XY: (-9500,4600)
C180 = C: ASSEMBLY: USB3_TYPEA; CDS_LIB: discrete; CDS_PART_NAME: C_0603-4.7UF,X5R,20%,6.3V,032-0886-000; CDS_PHYS_PART_NAME: C_0603-4.7UF,X5R,20%,6.3V,032-0886-000-032-0886-000,4.7UF; CDS_SEC: 1; DEVICE_TYPENAME: C_0603-47UFX5R2063V032-0886-000-032-0886-00047UF; DRAWING: @P3449_B01_LIB.P3449_B01(SCH_1):PAGE8; MAT: X5R; MAX_VOLTAGE: 6.3V; NV_PN: 032-0886-000; PATH: I18; PHYS_PAGE: 8; ROT: 0; SEC: 1; SIGNAL_MODEL: nv_cap; TOL: 20%; VER: 2; XY: (-9500,5050)
C181 = C#1: ASSEMBLY: USB3_TYPEA; CDS_LIB: discrete; CDS_PART_NAME: C_0603-10UF,X5R,20%,6.3V,039-0135-000; CDS_PHYS_PART_NAME: C_0603-10UF,X5R,20%,6.3V,039-0135-000-039-0135-000,10UF; CDS_SEC: 1; CHIPS_PART_NAME: C; DEVICE_TYPENAME: C_0603-10UFX5R2063V039-0135-000-039-0135-00010UF; DRAWING: @P3449_B01_LIB.P3449_B01(SCH_1):PAGE8; MAT: X5R; MAX_VOLTAGE: 6.3V; NV_PN: 039-0135-000; PATH: I32; PHYS_PAGE: 8; ROT: 0; SEC: 1; SIGNAL_MODEL: nv_cap; TOL: 20%; VER: 1; XY: (-8000,1450)
C238 = C: ASSEMBLY: USB3_TYPEA; CDS_LIB: discrete; CDS_PART_NAME: C_0402-1UF,X5R,10%,10V,039-0140-000; CDS_PHYS_PART_NAME: C_0402-1UF,X5R,10%,10V,039-0140-000-039-0140-000,1UF; CDS_SEC: 1; DEVICE_TYPENAME: C_0402-1UFX5R1010V039-0140-000-039-0140-0001UF; DRAWING: @P3449_B01_LIB.P3449_B01(SCH_1):PAGE8; MAT: X5R; MAX_VOLTAGE: 10V; NV_PN: 039-0140-000; PATH: I83; PHYS_PAGE: 8; ROT: 0; SEC: 1; SIGNAL_MODEL: nv_cap; TOL: 10%; VER: 2; XY: (-2400,3650)
C239 = C: ASSEMBLY: USB3_TYPEA; CDS_LIB: discrete; CDS_PART_NAME: C_0402-0.1UF,X5R,10%,6.3V,039-0007-000; CDS_PHYS_PART_NAME: C_0402-0.1UF,X5R,10%,6.3V,039-0007-000-0.1UF,039-0007-000; CDS_SEC: 1; DEVICE_TYPENAME: C_0402-01UFX5R1063V039-0007-000-01UF039-0007-000; DRAWING: @P3449_B01_LIB.P3449_B01(SCH_1):PAGE8; MAT: X5R; MAX_VOLTAGE: 6.3V; NV_PN: 039-0007-000; PATH: I84; PHYS_PAGE: 8; ROT: 0; SEC: 1; SIGNAL_MODEL: nv_cap; TOL: 10%; VER: 2; XY: (-2150,3550)
C248 = C: ASSEMBLY: USB3_TYPEA; CDS_LIB: discrete; CDS_PART_NAME: C_0402-22PF,C0G,5%,50V,035-0023-000; CDS_PHYS_PART_NAME: C_0402-22PF,C0G,5%,50V,035-0023-000-035-0023-000,22PF; CDS_SEC: 1; DEVICE_TYPENAME: C_0402-22PFC0G550V035-0023-000-035-0023-00022PF; DRAWING: @P3449_B01_LIB.P3449_B01(SCH_1):PAGE8; MAT: C0G; MAX_VOLTAGE: 50V; NV_PN: 035-0023-000; PATH: I86; PHYS_PAGE: 8; ROT: 0; SEC: 1; SIGNAL_MODEL: nv_cap; TOL: 5%; VER: 2; XY: (-2200,5100)
C249 = C: ASSEMBLY: USB3_TYPEA; CDS_LIB: discrete; CDS_PART_NAME: C_0402-22PF,C0G,5%,50V,035-0023-000; CDS_PHYS_PART_NAME: C_0402-22PF,C0G,5%,50V,035-0023-000-035-0023-000,22PF; CDS_SEC: 1; DEVICE_TYPENAME: C_0402-22PFC0G550V035-0023-000-035-0023-00022PF; DRAWING: @P3449_B01_LIB.P3449_B01(SCH_1):PAGE8; MAT: C0G; MAX_VOLTAGE: 50V; NV_PN: 035-0023-000; PATH: I87; PHYS_PAGE: 8; ROT: 0; SEC: 1; SIGNAL_MODEL: nv_cap; TOL: 5%; VER: 2; XY: (-1400,5100)
C253 = C: ASSEMBLY: USB3_TYPEA; CDS_LIB: discrete; CDS_PART_NAME: C_0402-0.1UF,X5R,10%,6.3V,039-0007-000; CDS_PHYS_PART_NAME: C_0402-0.1UF,X5R,10%,6.3V,039-0007-000-0.1UF,039-0007-000; CDS_SEC: 1; DEVICE_TYPENAME: C_0402-01UFX5R1063V039-0007-000-01UF039-0007-000; DRAWING: @P3449_B01_LIB.P3449_B01(SCH_1):PAGE8; MAT: X5R; MAX_VOLTAGE: 6.3V; NV_PN: 039-0007-000; PATH: I99; PHYS_PAGE: 8; ROT: 0; SEC: 1; SIGNAL_MODEL: nv_cap; TOL: 10%; VER: 2; XY: (-9500,6650)
C254 = C: ASSEMBLY: USB3_TYPEA; CDS_LIB: discrete; CDS_PART_NAME: C_0402-0.1UF,X5R,10%,6.3V,039-0007-000; CDS_PHYS_PART_NAME: C_0402-0.1UF,X5R,10%,6.3V,039-0007-000-0.1UF,039-0007-000; CDS_SEC: 1; DEVICE_TYPENAME: C_0402-01UFX5R1063V039-0007-000-01UF039-0007-000; DRAWING: @P3449_B01_LIB.P3449_B01(SCH_1):PAGE8; MAT: X5R; MAX_VOLTAGE: 6.3V; NV_PN: 039-0007-000; PATH: I100; PHYS_PAGE: 8; ROT: 0; SEC: 1; SIGNAL_MODEL: nv_cap; TOL: 10%; VER: 2; XY: (-9500,6500)
C255 = C: ASSEMBLY: USB3_TYPEA; CDS_LIB: discrete; CDS_PART_NAME: C_0402-0.1UF,X5R,10%,6.3V,039-0007-000; CDS_PHYS_PART_NAME: C_0402-0.1UF,X5R,10%,6.3V,039-0007-000-0.1UF,039-0007-000; CDS_SEC: 1; DEVICE_TYPENAME: C_0402-01UFX5R1063V039-0007-000-01UF039-0007-000; DRAWING: @P3449_B01_LIB.P3449_B01(SCH_1):PAGE8; MAT: X5R; MAX_VOLTAGE: 6.3V; NV_PN: 039-0007-000; PATH: I101; PHYS_PAGE: 8; ROT: 0; SEC: 1; SIGNAL_MODEL: nv_cap; TOL: 10%; VER: 2; XY: (-9500,6350)
C256 = C: ASSEMBLY: USB3_TYPEA; CDS_LIB: discrete; CDS_PART_NAME: C_0402-0.1UF,X5R,10%,6.3V,039-0007-000; CDS_PHYS_PART_NAME: C_0402-0.1UF,X5R,10%,6.3V,039-0007-000-0.1UF,039-0007-000; CDS_SEC: 1; DEVICE_TYPENAME: C_0402-01UFX5R1063V039-0007-000-01UF039-0007-000; DRAWING: @P3449_B01_LIB.P3449_B01(SCH_1):PAGE8; MAT: X5R; MAX_VOLTAGE: 6.3V; NV_PN: 039-0007-000; PATH: I102; PHYS_PAGE: 8; ROT: 0; SEC: 1; SIGNAL_MODEL: nv_cap; TOL: 10%; VER: 2; XY: (-9500,6200)
C257 = C: ASSEMBLY: USB3_TYPEA; CDS_LIB: discrete; CDS_PART_NAME: C_0402-0.1UF,X5R,10%,6.3V,039-0007-000; CDS_PHYS_PART_NAME: C_0402-0.1UF,X5R,10%,6.3V,039-0007-000-0.1UF,039-0007-000; CDS_SEC: 1; DEVICE_TYPENAME: C_0402-01UFX5R1063V039-0007-000-01UF039-0007-000; DRAWING: @P3449_B01_LIB.P3449_B01(SCH_1):PAGE8; MAT: X5R; MAX_VOLTAGE: 6.3V; NV_PN: 039-0007-000; PATH: I103; PHYS_PAGE: 8; ROT: 0; SEC: 1; SIGNAL_MODEL: nv_cap; TOL: 10%; VER: 2; XY: (-9500,6050)
C258 = C: ASSEMBLY: USB3_TYPEA; CDS_LIB: discrete; CDS_PART_NAME: C_0402-0.1UF,X5R,10%,6.3V,039-0007-000; CDS_PHYS_PART_NAME: C_0402-0.1UF,X5R,10%,6.3V,039-0007-000-0.1UF,039-0007-000; CDS_SEC: 1; DEVICE_TYPENAME: C_0402-01UFX5R1063V039-0007-000-01UF039-0007-000; DRAWING: @P3449_B01_LIB.P3449_B01(SCH_1):PAGE8; MAT: X5R; MAX_VOLTAGE: 6.3V; NV_PN: 039-0007-000; PATH: I104; PHYS_PAGE: 8; ROT: 0; SEC: 1; SIGNAL_MODEL: nv_cap; TOL: 10%; VER: 2; XY: (-9500,5900)
C259 = C: ASSEMBLY: USB3_TYPEA; CDS_LIB: discrete; CDS_PART_NAME: C_0402-0.1UF,X5R,10%,6.3V,039-0007-000; CDS_PHYS_PART_NAME: C_0402-0.1UF,X5R,10%,6.3V,039-0007-000-0.1UF,039-0007-000; CDS_SEC: 1; DEVICE_TYPENAME: C_0402-01UFX5R1063V039-0007-000-01UF039-0007-000; DRAWING: @P3449_B01_LIB.P3449_B01(SCH_1):PAGE8; MAT: X5R; MAX_VOLTAGE: 6.3V; NV_PN: 039-0007-000; PATH: I105; PHYS_PAGE: 8; ROT: 0; SEC: 1; SIGNAL_MODEL: nv_cap; TOL: 10%; VER: 2; XY: (-9500,5750)
C260 = C: ASSEMBLY: USB3_TYPEA; CDS_LIB: discrete; CDS_PART_NAME: C_0402-0.1UF,X5R,10%,6.3V,039-0007-000; CDS_PHYS_PART_NAME: C_0402-0.1UF,X5R,10%,6.3V,039-0007-000-0.1UF,039-0007-000; CDS_SEC: 1; DEVICE_TYPENAME: C_0402-01UFX5R1063V039-0007-000-01UF039-0007-000; DRAWING: @P3449_B01_LIB.P3449_B01(SCH_1):PAGE8; MAT: X5R; MAX_VOLTAGE: 6.3V; NV_PN: 039-0007-000; PATH: I118; PHYS_PAGE: 8; ROT: 0; SEC: 1; SIGNAL_MODEL: nv_cap; TOL: 10%; VER: 2; XY: (-9500,5200)
C261 = C: ASSEMBLY: USB3_TYPEA; CDS_LIB: discrete; CDS_PART_NAME: C_0402-0.1UF,X5R,10%,6.3V,039-0007-000; CDS_PHYS_PART_NAME: C_0402-0.1UF,X5R,10%,6.3V,039-0007-000-0.1UF,039-0007-000; CDS_SEC: 1; DEVICE_TYPENAME: C_0402-01UFX5R1063V039-0007-000-01UF039-0007-000; DRAWING: @P3449_B01_LIB.P3449_B01(SCH_1):PAGE8; MAT: X5R; MAX_VOLTAGE: 6.3V; NV_PN: 039-0007-000; PATH: I122; PHYS_PAGE: 8; ROT: 0; SEC: 1; SIGNAL_MODEL: nv_cap; TOL: 10%; VER: 2; XY: (-9500,4450)
C262 = C: ASSEMBLY: USB3_TYPEA; CDS_LIB: discrete; CDS_PART_NAME: C_0402-0.1UF,X5R,10%,6.3V,039-0007-000; CDS_PHYS_PART_NAME: C_0402-0.1UF,X5R,10%,6.3V,039-0007-000-0.1UF,039-0007-000; CDS_SEC: 1; DEVICE_TYPENAME: C_0402-01UFX5R1063V039-0007-000-01UF039-0007-000; DRAWING: @P3449_B01_LIB.P3449_B01(SCH_1):PAGE8; MAT: X5R; MAX_VOLTAGE: 6.3V; NV_PN: 039-0007-000; PATH: I123; PHYS_PAGE: 8; ROT: 0; SEC: 1; SIGNAL_MODEL: nv_cap; TOL: 10%; VER: 2; XY: (-9500,4300)
C263 = C: ASSEMBLY: USB3_TYPEA; CDS_LIB: discrete; CDS_PART_NAME: C_0402-0.1UF,X5R,10%,6.3V,039-0007-000; CDS_PHYS_PART_NAME: C_0402-0.1UF,X5R,10%,6.3V,039-0007-000-0.1UF,039-0007-000; CDS_SEC: 1; DEVICE_TYPENAME: C_0402-01UFX5R1063V039-0007-000-01UF039-0007-000; DRAWING: @P3449_B01_LIB.P3449_B01(SCH_1):PAGE8; MAT: X5R; MAX_VOLTAGE: 6.3V; NV_PN: 039-0007-000; PATH: I120; PHYS_PAGE: 8; ROT: 0; SEC: 1; SIGNAL_MODEL: nv_cap; TOL: 10%; VER: 2; XY: (-9500,4150)
L18 = L: ACOUSTIC_MARGIN: [ ]; ASSEMBLY: USB3_TYPEA; CDS_LIB: discrete; CDS_PART_NAME: L_2016-4.7UH,[ ],20%,0.2A,0.9A,0.16OHM,[ ]@[ ],[ ],131-0436-000; CDS_PHYS_PART_NAME: L_2016-4.7UH,[ ],20%,0.2A,0.9A,0.16OHM,[ ]@[ ],[ ],131-0436-000-131-0436-000,4.7UH; CDS_SEC: 1; CONTINUOUS_CURRENT: 0.2A; DC_RESISTANCE: 0.16ohm; DEVICE_TYPENAME: L_2016-47UH2002A09A016OHM131-0436-000-131-0436-00047UH; DRAWING: @P3449_B01_LIB.P3449_B01(SCH_1):PAGE8; MAT: [ ]; MAX_CURRENT: 0.9A; NV_PN: 131-0436-000; PACK_TYPE: 2016; PATH: I31; PHYS_PAGE: 8; Q: [ ]@[ ]; ROT: 0; SEC: 1; SELF_RESONANCE_FREQ: [ ]; SIGNAL_MODEL: nv_ind; TOL: 20%; VER: 1; XY: (-8400,1650)
Q28 = Q_FET_N_ENH#1: ASSEMBLY: USB3_TYPEA; CDS_LIB: discrete; CDS_PART_NAME: Q_FET_N_ENH_DFN1006-DMN26D0UFB4,20V,999MOHM@10V / 3000MOHM@4.5V / 4000MOHM@2.5V,0.14A,0.805A,10V,0.35W,999NC@10V / 0NC@4.5V / A; CDS_PHYS_PART_NAME: Q_FET_N_ENH_DFN1006-DMN26D0UFB4,20V,999MOHM@10V / 3000MOHM@4.5V / 4000MOHM@2.5V,0.14A,0.805A,10V,0.35W,999NC@10V / 0NC@4.5V / B; CDS_SEC: 1; CONTINUOUS_CURRENT: 0.14A; CaptureCellPackProp: Q_FET_N_ENH##1; DEVICE_TYPENAME: Q_FET_N_ENH_DFN1006-DMN26D0UFB420V999MOHM10V3000MOHM45V4000MOHM25V014A0805A10V035W999NC10V0NC45VB; DRAWING: @P3449_B01_LIB.P3449_B01(SCH_1):PAGE8; MAX_CURRENT: 0.805A; MAX_VOLTAGE: 20V; MAX_WATTAGE: 0.35W; NV_NAME: DMN26D0UFB4; NV_PN: 300-0868-000; PACK_TYPE: DFN1006; PATH: I92; PHYS_PAGE: 8; Q_G: 999nC@10V / 0nC@4.5V / 999nC@2.5V; ROT: 2; R_DS_ON: 999mohm@10V / 3000mohm@4.5V / 4000mohm@2.5V; SEC: 1; VER: 2; V_BE_GS: 10V; XY: (-2500,6600)
Q44 = Q_FET_N_ENH#1: ASSEMBLY: USB3_TYPEA; CDS_LIB: discrete; CDS_PART_NAME: Q_FET_N_ENH_DFN1006-DMN26D0UFB4,20V,999MOHM@10V / 3000MOHM@4.5V / 4000MOHM@2.5V,0.14A,0.805A,10V,0.35W,999NC@10V / 0NC@4.5V / A; CDS_PHYS_PART_NAME: Q_FET_N_ENH_DFN1006-DMN26D0UFB4,20V,999MOHM@10V / 3000MOHM@4.5V / 4000MOHM@2.5V,0.14A,0.805A,10V,0.35W,999NC@10V / 0NC@4.5V / B; CDS_SEC: 1; CONTINUOUS_CURRENT: 0.14A; CaptureCellPackProp: Q_FET_N_ENH##1; DEVICE_TYPENAME: Q_FET_N_ENH_DFN1006-DMN26D0UFB420V999MOHM10V3000MOHM45V4000MOHM25V014A0805A10V035W999NC10V0NC45VB; DRAWING: @P3449_B01_LIB.P3449_B01(SCH_1):PAGE8; MAX_CURRENT: 0.805A; MAX_VOLTAGE: 20V; MAX_WATTAGE: 0.35W; NV_NAME: DMN26D0UFB4; NV_PN: 300-0868-000; PACK_TYPE: DFN1006; PATH: I138; PHYS_PAGE: 8; Q_G: 999nC@10V / 0nC@4.5V / 999nC@2.5V; ROT: 2; R_DS_ON: 999mohm@10V / 3000mohm@4.5V / 4000mohm@2.5V; SEC: 1; VER: 2; V_BE_GS: 10V; XY: (-1700,6450)
R269 = R#1: ASSEMBLY: USB3_TYPEA; CDS_LIB: discrete; CDS_PART_NAME: R_0402-6.19K,1 %,62.5MW,195-0384-000; CDS_PHYS_PART_NAME: R_0402-6.19K,1 %,62.5MW,195-0384-000-195-0384-000,6.19K; CDS_SEC: 1; CHIPS_PART_NAME: R; DEVICE_TYPENAME: R_0402-619K1625MW195-0384-000-195-0384-000619K; DRAWING: @P3449_B01_LIB.P3449_B01(SCH_1):PAGE8; MAX_WATTAGE: 62.5mW; NV_PN: 195-0384-000; PATH: I36; PHYS_PAGE: 8; ROT: 0; SEC: 1; SIGNAL_MODEL: nv_res; TOL: 1%; VER: 1; XY: (-5400,3350)
R348 = R#1: ASSEMBLY: USB3_TYPEA; CDS_LIB: discrete; CDS_PART_NAME: R_0402-10K,5 %,62.5MW,195-0486-000; CDS_PHYS_PART_NAME: R_0402-10K,5 %,62.5MW,195-0486-000-10K,195-0486-000; CDS_SEC: 1; CHIPS_PART_NAME: R; DEVICE_TYPENAME: R_0402-10K5625MW195-0486-000-10K195-0486-000; DRAWING: @P3449_B01_LIB.P3449_B01(SCH_1):PAGE8; MAX_WATTAGE: 62.5mW; NV_PN: 195-0486-000; PATH: I95; PHYS_PAGE: 8; ROT: 0; SEC: 1; SIGNAL_MODEL: nv_res; TOL: 5%; VER: 1; XY: (-4200,6750)
R349 = R#1: ASSEMBLY: USB3_TYPEA; CDS_LIB: discrete; CDS_PART_NAME: R_0402-10K,5 %,62.5MW,195-0486-000; CDS_PHYS_PART_NAME: R_0402-10K,5 %,62.5MW,195-0486-000-10K,195-0486-000; CDS_SEC: 1; CHIPS_PART_NAME: R; DEVICE_TYPENAME: R_0402-10K5625MW195-0486-000-10K195-0486-000; DRAWING: @P3449_B01_LIB.P3449_B01(SCH_1):PAGE8; MAX_WATTAGE: 62.5mW; NV_PN: 195-0486-000; PATH: I96; PHYS_PAGE: 8; ROT: 0; SEC: 1; SIGNAL_MODEL: nv_res; TOL: 5%; VER: 1; XY: (-4250,6300)
R350 = R#1: ASSEMBLY: USB3_TYPEA; CDS_LIB: discrete; CDS_PART_NAME: R_0402-100K,1 %,62.5MW,195-0005-000; CDS_PHYS_PART_NAME: R_0402-100K,1 %,62.5MW,195-0005-000-100K,195-0005-000; CDS_SEC: 1; CHIPS_PART_NAME: R; DEVICE_TYPENAME: R_0402-100K1625MW195-0005-000-100K195-0005-000; DRAWING: @P3449_B01_LIB.P3449_B01(SCH_1):PAGE8; MAX_WATTAGE: 62.5mW; NV_PN: 195-0005-000; PATH: I91; PHYS_PAGE: 8; ROT: 0; SEC: 1; SIGNAL_MODEL: nv_res; TOL: 1%; VER: 1; XY: (-1450,6850)
R354 = R: ASSEMBLY: USB3_TYPEA; CDS_LIB: discrete; CDS_PART_NAME: R_0402-100K,1 %,62.5MW,195-0005-000; CDS_PHYS_PART_NAME: R_0402-100K,1 %,62.5MW,195-0005-000-100K,195-0005-000; CDS_SEC: 1; DEVICE_TYPENAME: R_0402-100K1625MW195-0005-000-100K195-0005-000; DRAWING: @P3449_B01_LIB.P3449_B01(SCH_1):PAGE8; MAX_WATTAGE: 62.5mW; NV_PN: 195-0005-000; PATH: I130; PHYS_PAGE: 8; ROT: 0; SEC: 1; SIGNAL_MODEL: nv_res; TOL: 1%; VER: 2; XY: (-4800,5200)
R465 = R#1: ASSEMBLY: USB3_TYPEA; CDS_LIB: discrete; CDS_PART_NAME: R_0402-10K,5 %,62.5MW,195-0486-000; CDS_PHYS_PART_NAME: R_0402-10K,5 %,62.5MW,195-0486-000-10K,195-0486-000; CDS_SEC: 1; CHIPS_PART_NAME: R; DEVICE_TYPENAME: R_0402-10K5625MW195-0486-000-10K195-0486-000; DRAWING: @P3449_B01_LIB.P3449_B01(SCH_1):PAGE8; MAX_WATTAGE: 62.5mW; NV_PN: 195-0486-000; PATH: I141; PHYS_PAGE: 8; ROT: 0; SEC: 1; SIGNAL_MODEL: nv_res; TOL: 5%; VER: 1; XY: (-6600,3750)
U27 = U_USB_HUB_RTS5411S: ASSEMBLY: USB3_TYPEA; CDS_LIB: digital; CDS_PART_NAME: U_USB_HUB_RTS5411S_QFN76-RTS5411S-GRT,USB,115-2628-000; CDS_PHYS_PART_NAME: U_USB_HUB_RTS5411S_QFN76-RTS5411S-GRT,USB,115-2628-000-115-2628-000; CDS_SEC: 2; CaptureCellPackProp: U_USB_HUB_RTS5411SA; DEVICE_TYPENAME: U_USB_HUB_RTS5411S_QFN76-RTS5411S-GRTUSB115-2628-000-115-2628-000; DRAWING: @P3449_B01_LIB.P3449_B01(SCH_1):PAGE8; NV_NAME: RTS5411S-GRT; NV_PN: 115-2628-000; PACK_TYPE: QFN76; PATH: I136; PHYS_PAGE: 8; ROT: 0; SEC: 2; TYPE: USB; VER: 2; XY: (-4150,2550)
VS1 = VIRTUAL_SHORT: CDS_LIB: mechanic; CDS_PART_NAME: VIRTUAL_SHORT_SHUNT-VIRTUAL_SHORT; CDS_PHYS_PART_NAME: VIRTUAL_SHORT_SHUNT-VIRTUAL_SHORT; CDS_SEC: 1; DEVICE_TYPENAME: VIRTUAL_SHORT_SHUNT-VIRTUAL_SHORT; DRAWING: @P3449_B01_LIB.P3449_B01(SCH_1):PAGE8; PACK_TYPE: SHUNT; PATH: I97; PHYS_PAGE: 8; ROT: 0; SEC: 1; VER: 1; XY: (-10500,6800)
VS2 = VIRTUAL_SHORT: CDS_LIB: mechanic; CDS_PART_NAME: VIRTUAL_SHORT_SHUNT-VIRTUAL_SHORT; CDS_PHYS_PART_NAME: VIRTUAL_SHORT_SHUNT-VIRTUAL_SHORT; CDS_SEC: 1; DEVICE_TYPENAME: VIRTUAL_SHORT_SHUNT-VIRTUAL_SHORT; DRAWING: @P3449_B01_LIB.P3449_B01(SCH_1):PAGE8; PACK_TYPE: SHUNT; PATH: I98; PHYS_PAGE: 8; ROT: 0; SEC: 1; VER: 1; XY: (-10500,6650)
VS3 = VIRTUAL_SHORT: CDS_LIB: mechanic; CDS_PART_NAME: VIRTUAL_SHORT_SHUNT-VIRTUAL_SHORT; CDS_PHYS_PART_NAME: VIRTUAL_SHORT_SHUNT-VIRTUAL_SHORT; CDS_SEC: 1; DEVICE_TYPENAME: VIRTUAL_SHORT_SHUNT-VIRTUAL_SHORT; DRAWING: @P3449_B01_LIB.P3449_B01(SCH_1):PAGE8; PACK_TYPE: SHUNT; PATH: I106; PHYS_PAGE: 8; ROT: 0; SEC: 1; VER: 1; XY: (-10500,6500)
VS4 = VIRTUAL_SHORT: CDS_LIB: mechanic; CDS_PART_NAME: VIRTUAL_SHORT_SHUNT-VIRTUAL_SHORT; CDS_PHYS_PART_NAME: VIRTUAL_SHORT_SHUNT-VIRTUAL_SHORT; CDS_SEC: 1; DEVICE_TYPENAME: VIRTUAL_SHORT_SHUNT-VIRTUAL_SHORT; DRAWING: @P3449_B01_LIB.P3449_B01(SCH_1):PAGE8; PACK_TYPE: SHUNT; PATH: I107; PHYS_PAGE: 8; ROT: 0; SEC: 1; VER: 1; XY: (-10500,6350)
VS5 = VIRTUAL_SHORT: CDS_LIB: mechanic; CDS_PART_NAME: VIRTUAL_SHORT_SHUNT-VIRTUAL_SHORT; CDS_PHYS_PART_NAME: VIRTUAL_SHORT_SHUNT-VIRTUAL_SHORT; CDS_SEC: 1; DEVICE_TYPENAME: VIRTUAL_SHORT_SHUNT-VIRTUAL_SHORT; DRAWING: @P3449_B01_LIB.P3449_B01(SCH_1):PAGE8; PACK_TYPE: SHUNT; PATH: I108; PHYS_PAGE: 8; ROT: 0; SEC: 1; VER: 1; XY: (-10500,6200)
VS6 = VIRTUAL_SHORT: CDS_LIB: mechanic; CDS_PART_NAME: VIRTUAL_SHORT_SHUNT-VIRTUAL_SHORT; CDS_PHYS_PART_NAME: VIRTUAL_SHORT_SHUNT-VIRTUAL_SHORT; CDS_SEC: 1; DEVICE_TYPENAME: VIRTUAL_SHORT_SHUNT-VIRTUAL_SHORT; DRAWING: @P3449_B01_LIB.P3449_B01(SCH_1):PAGE8; PACK_TYPE: SHUNT; PATH: I134; PHYS_PAGE: 8; ROT: 0; SEC: 1; VER: 1; XY: (-10500,6050)
VS7 = VIRTUAL_SHORT: CDS_LIB: mechanic; CDS_PART_NAME: VIRTUAL_SHORT_SHUNT-VIRTUAL_SHORT; CDS_PHYS_PART_NAME: VIRTUAL_SHORT_SHUNT-VIRTUAL_SHORT; CDS_SEC: 1; DEVICE_TYPENAME: VIRTUAL_SHORT_SHUNT-VIRTUAL_SHORT; DRAWING: @P3449_B01_LIB.P3449_B01(SCH_1):PAGE8; PACK_TYPE: SHUNT; PATH: I110; PHYS_PAGE: 8; ROT: 0; SEC: 1; VER: 1; XY: (-10500,5900)
VS8 = VIRTUAL_SHORT: CDS_LIB: mechanic; CDS_PART_NAME: VIRTUAL_SHORT_SHUNT-VIRTUAL_SHORT; CDS_PHYS_PART_NAME: VIRTUAL_SHORT_SHUNT-VIRTUAL_SHORT; CDS_SEC: 1; DEVICE_TYPENAME: VIRTUAL_SHORT_SHUNT-VIRTUAL_SHORT; DRAWING: @P3449_B01_LIB.P3449_B01(SCH_1):PAGE8; PACK_TYPE: SHUNT; PATH: I112; PHYS_PAGE: 8; ROT: 0; SEC: 1; VER: 1; XY: (-10500,5750)
VS9 = VIRTUAL_SHORT: CDS_LIB: mechanic; CDS_PART_NAME: VIRTUAL_SHORT_SHUNT-VIRTUAL_SHORT; CDS_PHYS_PART_NAME: VIRTUAL_SHORT_SHUNT-VIRTUAL_SHORT; CDS_SEC: 1; DEVICE_TYPENAME: VIRTUAL_SHORT_SHUNT-VIRTUAL_SHORT; DRAWING: @P3449_B01_LIB.P3449_B01(SCH_1):PAGE8; PACK_TYPE: SHUNT; PATH: I114; PHYS_PAGE: 8; ROT: 0; SEC: 1; VER: 1; XY: (-10500,5350)
VS10 = VIRTUAL_SHORT: CDS_LIB: mechanic; CDS_PART_NAME: VIRTUAL_SHORT_SHUNT-VIRTUAL_SHORT; CDS_PHYS_PART_NAME: VIRTUAL_SHORT_SHUNT-VIRTUAL_SHORT; CDS_SEC: 1; DEVICE_TYPENAME: VIRTUAL_SHORT_SHUNT-VIRTUAL_SHORT; DRAWING: @P3449_B01_LIB.P3449_B01(SCH_1):PAGE8; PACK_TYPE: SHUNT; PATH: I115; PHYS_PAGE: 8; ROT: 0; SEC: 1; VER: 1; XY: (-10500,5200)
VS11 = VIRTUAL_SHORT: CDS_LIB: mechanic; CDS_PART_NAME: VIRTUAL_SHORT_SHUNT-VIRTUAL_SHORT; CDS_PHYS_PART_NAME: VIRTUAL_SHORT_SHUNT-VIRTUAL_SHORT; CDS_SEC: 1; DEVICE_TYPENAME: VIRTUAL_SHORT_SHUNT-VIRTUAL_SHORT; DRAWING: @P3449_B01_LIB.P3449_B01(SCH_1):PAGE8; PACK_TYPE: SHUNT; PATH: I116; PHYS_PAGE: 8; ROT: 0; SEC: 1; VER: 1; XY: (-10500,5050)
VS12 = VIRTUAL_SHORT: CDS_LIB: mechanic; CDS_PART_NAME: VIRTUAL_SHORT_SHUNT-VIRTUAL_SHORT; CDS_PHYS_PART_NAME: VIRTUAL_SHORT_SHUNT-VIRTUAL_SHORT; CDS_SEC: 1; DEVICE_TYPENAME: VIRTUAL_SHORT_SHUNT-VIRTUAL_SHORT; DRAWING: @P3449_B01_LIB.P3449_B01(SCH_1):PAGE8; PACK_TYPE: SHUNT; PATH: I124; PHYS_PAGE: 8; ROT: 0; SEC: 1; VER: 1; XY: (-10500,4600)
VS13 = VIRTUAL_SHORT: CDS_LIB: mechanic; CDS_PART_NAME: VIRTUAL_SHORT_SHUNT-VIRTUAL_SHORT; CDS_PHYS_PART_NAME: VIRTUAL_SHORT_SHUNT-VIRTUAL_SHORT; CDS_SEC: 1; DEVICE_TYPENAME: VIRTUAL_SHORT_SHUNT-VIRTUAL_SHORT; DRAWING: @P3449_B01_LIB.P3449_B01(SCH_1):PAGE8; PACK_TYPE: SHUNT; PATH: I125; PHYS_PAGE: 8; ROT: 0; SEC: 1; VER: 1; XY: (-10500,4450)
VS14 = VIRTUAL_SHORT: CDS_LIB: mechanic; CDS_PART_NAME: VIRTUAL_SHORT_SHUNT-VIRTUAL_SHORT; CDS_PHYS_PART_NAME: VIRTUAL_SHORT_SHUNT-VIRTUAL_SHORT; CDS_SEC: 1; DEVICE_TYPENAME: VIRTUAL_SHORT_SHUNT-VIRTUAL_SHORT; DRAWING: @P3449_B01_LIB.P3449_B01(SCH_1):PAGE8; PACK_TYPE: SHUNT; PATH: I126; PHYS_PAGE: 8; ROT: 0; SEC: 1; VER: 1; XY: (-10500,4300)
VS15 = VIRTUAL_SHORT: CDS_LIB: mechanic; CDS_PART_NAME: VIRTUAL_SHORT_SHUNT-VIRTUAL_SHORT; CDS_PHYS_PART_NAME: VIRTUAL_SHORT_SHUNT-VIRTUAL_SHORT; CDS_SEC: 1; DEVICE_TYPENAME: VIRTUAL_SHORT_SHUNT-VIRTUAL_SHORT; DRAWING: @P3449_B01_LIB.P3449_B01(SCH_1):PAGE8; PACK_TYPE: SHUNT; PATH: I127; PHYS_PAGE: 8; ROT: 0; SEC: 1; VER: 1; XY: (-10500,4150)
Y1 = XTAL_4PIN: ASSEMBLY: USB3_TYPEA; CDS_LIB: clocks; CDS_PART_NAME: XTAL_4PIN_SMD_32X25-EXS00A-CS11273,12MHZ,15PPM,5PPM,50PPM,10PF,FUNDAMENTAL,085-0328-000; CDS_PHYS_PART_NAME: XTAL_4PIN_SMD_32X25-EXS00A-CS11273,12MHZ,15PPM,5PPM,50PPM,10PF,FUNDAMENTAL,085-0328-000-085-0328-000,12MHZ; CDS_SEC: 1; DEVICE_TYPENAME: XTAL_4PIN_SMD_32X25-EXS00A-CS1127312MHZ15PPM5PPM50PPM10PFFUNDAMENTAL085-0328-000-085-0328-00012MHZ; DRAWING: @P3449_B01_LIB.P3449_B01(SCH_1):PAGE8; LOAD_CAPACITANCE: 10pF; NV_NAME: EXS00A-CS11273; NV_PN: 085-0328-000; OVERTONE: Fundamental; PACK_TYPE: SMD_32X25; PATH: I85; PHYS_PAGE: 8; ROT: 0; SEC: 1; SEC_TYPE: SMD_32X25; TOL: 15ppm; TOL_AGE: 5ppm; TOL_TOTAL: 50ppm; VER: 2; XY: (-1800,5250)

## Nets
3V3_IO_PG: Q44.1(G) ; also on sheet 6 11
AV12_1: C171.1 U27.7(AV12_1) VS1.2(B)
AV12_2: C253.1 U27.13(AV12_2) VS2.2(B)
AV12_3: C254.1 U27.19(AV12_3) VS3.2(B)
AV12_4: C255.1 U27.25(AV12_4) VS4.2(B)
AV12_5: C256.1 U27.31(AV12_5) VS5.2(B)
AV12_6: C257.1 U27.58(AV12_6) VS6.2(B)
AV12_7: C258.1 U27.64(AV12_7) VS7.2(B)
AV12_8: C259.1 U27.70(AV12_8) VS8.2(B)
DV12_1: C172.1 U27.3(DV12_1) VS9.2(B)
DV12_2: C260.1 U27.49(DV12_2) VS10.2(B)
DV12_3: C180.1 U27.50(DV12_3) VS11.2(B)
DV33_1: C173.1 U27.4(DV33_1) VS12.2(B)
DV33_2: C261.1 U27.22(DV33_2) VS13.2(B)
DV33_3: C262.1 U27.48(DV33_3) VS14.2(B)
DV33_4: C263.1 U27.73(DV33_4) VS15.2(B)
GND: C120.2 C123.2 C124.2 C125.2 C147.2 C171.2 C172.2 C173.2 C180.2 C181.2 C248.2 C249.1 C253.2 C254.2 C255.2 C256.2 C257.2 C258.2 C259.2 C260.2 C261.2 C262.2 C263.2 C311.2 D11.2 D21.2 D22.2 J28.5(GND) J28.6(SH1) J28.7(SH2) J28.8(SH3) J28.9(SH4) J47.25A(SH1) J47.25B(SH2) J47.26A(SH3) J47.26B(SH4) J47.27(SH5) J47.28(SH6) J47.A1(GND1) J47.A12(GND2) J47.B1(GND3) J47.B12(GND4) Q28.2(S) Q42.2(S) Q44.2(S) R269.1 R435.2 R439.2 R440.2 R465.1 U27.51(SWR_GND) U27.61(GND) U27.77(E_PAD) Y1.2 Y1.4 ; also on sheet 1 3 4 5 6 7 8 9 10 11 12 13 14 19
VBUS_DET: Q42.1(G) R434.2 R435.1
VDD_5V_IN: C123.1 C125.1 U27.53(SWR_V5_IN) U27.54(LDO_V5_IN) ; also on sheet 3 4 7 10 11 12 14 19
VDD_5V_USB: C147.1 C311.1 D11.1 J28.1(VBUS) J47.A4(VBUS1) J47.A9(VBUS2) J47.B4(VBUS3) J47.B9(VBUS4) R434.1 ; also on sheet 12
VDD_HUB_1V2: C181.1 L18.2 VS1.1(A) VS2.1(A) VS3.1(A) VS4.1(A) VS5.1(A) VS6.1(A) VS7.1(A) VS8.1(A) VS9.1(A) VS10.1(A) VS11.1(A)
VDD_HUB_3V3: C120.1 C124.1 R348.1 R349.1 R350.2 R354.1 U27.55(V33_OUT) VS12.1(A) VS13.1(A) VS14.1(A) VS15.1(A)
CAM_I2C_SCL: U27.32(GPIO0) ; also on sheet 5 18
CAM_I2C_SDA: U27.33(GPIO1) ; also on sheet 5 18
DP0_AUX_CH0_N: J2.90(DP_AUX_CH0_N) ; also on sheet 6
DP0_AUX_CH0_P: J2.92(DP_AUX_CH0_P) ; also on sheet 6
DP0_HPD: J2.88(DP_HPD) ; also on sheet 6
DP0_TXD0_N: J2.39(EDP_TXD0_N) ; also on sheet 6
DP0_TXD0_P: J2.41(EDP_TXD0_P) ; also on sheet 6
DP0_TXD1_N: J2.45(EDP_TXD1_N) ; also on sheet 6
DP0_TXD1_P: J2.47(EDP_TXD1_P) ; also on sheet 6
DP0_TXD2_N: J2.51(EDP_TXD2_N) ; also on sheet 6
DP0_TXD2_P: J2.53(EDP_TXD2_P) ; also on sheet 6
DP0_TXD3_N: J2.57(EDP_TXD3_N) ; also on sheet 6
DP0_TXD3_P: J2.59(EDP_TXD3_P) ; also on sheet 6
DSI_CLK_N: J2.76(DSI_A_CLK_N) TP76.1
DSI_CLK_P: J2.78(DSI_A_CLK_P) TP75.1
DSI_D0_N: J2.70(DSI_A_D0_N) TP78.1
DSI_D0_P: J2.72(DSI_A_D0_P) TP77.1
DSI_D1_N: J2.82(DSI_A_D1_N) TP80.1
DSI_D1_P: J2.84(DSI_A_D1_P) TP79.1
DSP1_DN: U27.72(DSP1_DM) ; also on sheet 14
DSP1_DP: U27.71(DSP1_DP) ; also on sheet 14
DSP1_SSRX_N: U27.69(DSP1_SSRX_N) ; also on sheet 14
DSP1_SSRX_P: U27.68(DSP1_SSRX_P) ; also on sheet 14
DSP1_SSTX_N: U27.66(DSP1_SSTX_N) ; also on sheet 14
DSP1_SSTX_P: U27.65(DSP1_SSTX_P) ; also on sheet 14
DSP2_DN: U27.6(DSP2_DM) ; also on sheet 14
DSP2_DP: U27.5(DSP2_DP) ; also on sheet 14
DSP2_SSRX_N: U27.12(DSP2_SSRX_N) ; also on sheet 14
DSP2_SSRX_P: U27.11(DSP2_SSRX_P) ; also on sheet 14
DSP2_SSTX_N: U27.9(DSP2_SSTX_N) ; also on sheet 14
DSP2_SSTX_P: U27.8(DSP2_SSTX_P) ; also on sheet 14
DSP3_DN: U27.21(DSP3_DM) ; also on sheet 13
DSP3_DP: U27.20(DSP3_DP) ; also on sheet 13
DSP3_SSRX_N: U27.18(DSP3_SSRX_N) ; also on sheet 13
DSP3_SSRX_P: U27.17(DSP3_SSRX_P) ; also on sheet 13
DSP3_SSTX_N: U27.15(DSP3_SSTX_N) ; also on sheet 13
DSP3_SSTX_P: U27.14(DSP3_SSTX_P) ; also on sheet 13
DSP4_DN: U27.24(DSP4_DM) ; also on sheet 13
DSP4_DP: U27.23(DSP4_DP) ; also on sheet 13
DSP4_SSRX_N: U27.30(DSP4_SSRX_N) ; also on sheet 13
DSP4_SSRX_P: U27.29(DSP4_SSRX_P) ; also on sheet 13
DSP4_SSTX_N: U27.27(DSP4_SSTX_N) ; also on sheet 13
DSP4_SSTX_P: U27.26(DSP4_SSTX_P) ; also on sheet 13
DSP1234_PWR: U27.40(DSP1_PWR) ; also on sheet 14
HDMI_CEC: J2.94(HDMI_CEC) ; also on sheet 7
HDMI_DDC_SCL_POL: J2.100(DP_AUX_CH1_P) ; also on sheet 7
HDMI_DDC_SDA_POL: J2.98(DP_AUX_CH1_N) ; also on sheet 7
HDMI_HPD: J2.96(HDMI_INT_DP_HPD) ; also on sheet 7
HDMI_TXC_N: J2.81(HDMI_TXC_N) ; also on sheet 7
HDMI_TXC_P: J2.83(HDMI_TXC_P) ; also on sheet 7
HDMI_TXD0_N: J2.75(HDMI_TXD2_N) ; also on sheet 7
HDMI_TXD0_P: J2.77(HDMI_TXD2_P) ; also on sheet 7
HDMI_TXD1_N: J2.69(HDMI_TXD1_N) ; also on sheet 7
HDMI_TXD1_P: J2.71(HDMI_TXD1_P) ; also on sheet 7
HDMI_TXD2_N: J2.63(HDMI_TXD0_N) ; also on sheet 7
HDMI_TXD2_P: J2.65(HDMI_TXD0_P) ; also on sheet 7
HUB_BPWR_DET: Q28.3(D) R348.2 U27.2(BPWR_DET)
HUB_SPWR_DET: R349.2 U27.76(SPWR_DET)
HUB_SWR_OUT: L18.1 U27.52(SWR_OUT)
HUB_XTAL_IN: C248.1 U27.74(XTLI) Y1.1
HUB_XTAL_OUT: C249.2 U27.75(XTLO) Y1.3
PCIE0_CLK_N: J2.160(PEX_CLK1_N) ; also on sheet 9
PCIE0_CLK_P: J2.162(PEX_CLK1_P) ; also on sheet 9
PCIE0_CLKREQ: J2.180(PEX_L0_CLKREQ) ; also on sheet 9
PCIE0_RST: J2.181(PEX_L0_RST) ; also on sheet 9
PCIE0_RX0_M2_N: J2.131(PEX_RX4_N) ; also on sheet 9
PCIE0_RX0_M2_P: J2.133(PEX_RX4_P) ; also on sheet 9
PCIE0_RX1_N: J2.137(PEX_RX3_N) ; also on sheet 2
PCIE0_RX1_P: J2.139(PEX_RX3_P) ; also on sheet 2
PCIE0_RX2_N: J2.149(PEX_RX2_N) ; also on sheet 2
PCIE0_RX2_P: J2.151(PEX_RX2_P) ; also on sheet 2
PCIE0_RX3_N: J2.155(PEX_RX1_N) ; also on sheet 2
PCIE0_RX3_P: J2.157(PEX_RX1_P) ; also on sheet 2
PCIE0_TX0_AP_N: J2.134(PEX_TX4_N) ; also on sheet 9
PCIE0_TX0_AP_P: J2.136(PEX_TX4_P) ; also on sheet 9
PCIE0_TX1_N: J2.140(PEX_TX3_N) ; also on sheet 2
PCIE0_TX1_P: J2.142(PEX_TX3_P) ; also on sheet 2
PCIE0_TX2_N: J2.148(PEX_TX2_N) ; also on sheet 2
PCIE0_TX2_P: J2.150(PEX_TX2_P) ; also on sheet 2
PCIE0_TX3_N: J2.154(PEX_TX1_N) ; also on sheet 2
PCIE0_TX3_P: J2.156(PEX_TX1_P) ; also on sheet 2
PCIE1_CLK_N: J2.173(PEX_CLK2_N) ; also on sheet 2
PCIE1_CLK_P: J2.175(PEX_CLK2_P) ; also on sheet 2
PCIE1_CLKREQ: J2.182(PEX_L1_CLKREQ) ; also on sheet 2
PCIE1_RST: J2.183(PEX_L1_RST) ; also on sheet 2
PCIE1_RX0_N: J2.167(PEX_RX0_N) ; also on sheet 2
PCIE1_RX0_P: J2.169(PEX_RX0_P) ; also on sheet 2
PCIE1_TX0_N: J2.172(PEX_TX0_N) ; also on sheet 2
PCIE1_TX0_P: J2.174(PEX_TX0_P) ; also on sheet 2
PCIE_WAKE: J2.179(PEX_WAKE) ; also on sheet 9
RREF: R269.2 U27.1(RREF)
SNN_DSP2_PWR: U27.41(DSP2_PWR)
SNN_DSP3_PWR: U27.42(DSP3_PWR)
SNN_DSP4_PWR: U27.43(DSP4_PWR)
SNN_HUB_GPIO2: U27.34(GPIO2)
SNN_HUB_GPIO3: U27.35(GPIO3)
SNN_HUB_GPIO4: U27.36(GPIO4)
SNN_HUB_GPIO5: U27.37(GPIO5)
SNN_HUB_GPIO6: U27.38(GPIO6)
SNN_HUB_GPIO7: U27.39(GPIO7)
SNN_SPI_HUB_MISO: U27.46(MISO)
SNN_SPI_HUB_MOSI: U27.47(MOSI)
SNN_SPI_HUB_SCK: U27.44(SCK)
SNN_USB0_ID_CONN: J28.4(ID)
SNN_USBC_RX1_N: J47.B10(SSRX1_N)
SNN_USBC_RX1_P: J47.B11(SSRX1_P)
SNN_USBC_RX2_N: J47.A10(SSRX2_N)
SNN_USBC_RX2_P: J47.A11(SSRX2_P)
SNN_USBC_SBU1: J47.A8(SBU1)
SNN_USBC_SBU2: J47.B8(SBU2)
SNN_USBC_TX1_N: J47.A3(SSTX1_N)
SNN_USBC_TX1_P: J47.A2(SSTX1_P)
SNN_USBC_TX2_N: J47.B3(SSTX2_N)
SNN_USBC_TX2_P: J47.B2(SSTX2_P)
SPI_HUB_CS: R465.2 U27.45(SCS)
SUSCLK_32KHZ: J2.210(CLK_32K_OUT) ; also on sheet 9
USB0_AP_N: D22.1 J28.2(DN) J47.A6(D1_P) J47.B7(D2_N) ; also on sheet 18
USB0_AP_P: D21.1 J28.3(DP) J47.A7(D1_N) J47.B6(D2_P) ; also on sheet 18
USB0_VBUS_DET*: Q42.3(D) ; also on sheet 18
USB1_AP_N: U27.57(USP_DM) ; also on sheet 18
USB1_AP_P: U27.56(USP_DP) ; also on sheet 18
USB_HUB_EN*: Q28.1(G) Q44.3(D) R350.1
USB_TYPEA_OCP: R354.2 U27.10(OCP2) U27.16(OCP3) U27.28(OCP4) U27.67(OCP1) ; also on sheet 14
USBC_CC1: J47.A5(CC1) R439.1
USBC_CC2: J47.B5(CC2) R440.1
USBSS_RX6_HUB_N: C238.1 U27.62(USP_SSRX_N)
USBSS_RX6_HUB_P: C239.1 U27.63(USP_SSRX_P)
USBSS_RX6_N: C8.1 J2.161(PEX_RX6_N)
USBSS_RX6_P: C6.1 J2.163(PEX_RX6_P)
USBSS_TX6_HUB_N: C8.2 U27.59(USP_SSTX_N)
USBSS_TX6_HUB_P: C6.2 U27.60(USP_SSTX_P)
USBSS_TX6_N: C238.2 J2.166(PEX_TX6_N)
USBSS_TX6_P: C239.2 J2.168(PEX_TX6_P)

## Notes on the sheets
sheet 15
- A
- B
- C
- D
- E
- F
- G
- H
- USB3.1 HUB x4 PORTS
- DECOUPLING CAPS
- RTS5411S POWER ON/OFF CONTROL
- BPWR_DET LOW:Disable
  RTS5411S
- BPWR_DET HIGH:Enable
  RTS5411S
- 1
- 1
- FOR AV12 PINS
- SELF POWER
  DETECTION
- 12MHz CRYSTAL FOR RTS5411S SYSTEM CLOCK
- PULL-UP FOR OCP
- 2
- 2
- FOR DV12 PINS
- FOR DV33 PINS
- 3
- 3
- Update RTS5411 eFUSE to make DSPx_PWR high active, as note below.
- 4
- 4
- 5
- I2C slave addrs: 7'1101010b = 7'h6A
- 5
- SPI Flash was removed from B01, customize RTS5411 internal eFuse (DSP1/2/3/4_PWR High active,
  disable charging feature, SSC valid) with Realtek tool.
- NVIDIA CORPORATION
- 2701 SAN TOMAS
  EXPRESSWAY
- ASSEMBLY
- <ASSEMBLY_DESCRIPTION>
- SANTA CLARA, CA 95050, USA
- PAGE DETAIL
- USB3.1 x4
  HUB
- NV_PN
- 600-13449-BASE-400
- ALL NVIDIA DESIGN SPECIFICATIONS, REFERENCE SPECIFICATIONS, REFERENCE BOARDS, FILES, DRAWINGS, DIAGNOSTICS, LISTS AND OTHER DOCUMENTS OR INFORMATION (TOGETHER AND SEPARATELY, 'MATERIALS') ARE BEING PROVIDED 'AS IS'. THE MATERIALS
  MAY
- CONTAIN KNOWN AND UNKNOWN VIOLATIONS OR DEVIATIONS OF INDUSTRY STANDARDS AND SPECIFICATIONS. NVIDIA MAKES NO WARRANTIES, EXPRESSED, IMPLIED, STATUTORY OR OTHERWISE WITH RESPECT TO THE MATERIALS OR OTHERWISE, AND EXPRESSLY DISCLAIMS
  ALL
- PCB REV
- P3449-B01
- PAGE
- 8 OF 23
- IMPLIED WARRANTIES INCLUDING, WITHOUT LIMITATION, THE WARRANTIES OF DESIGN, OF NONINFRINGEMENT, MERCHANTABILITY OR FITNESS FOR A PARTICULAR PURPOSE, OR ARISING FROM A COURSE OF DEALING, TRADE USAGE, TRADE PRACTICE, OR INDUSTRY
  STANDARDS.
- BOM REV
- M
- DATE
- 08-OCT-2022
- A
- B
- C
- D
- E
- F
- G
- H
sheet 16
- A
- B
- C
- D
- E
- F
- G
- H
- MICRO AB USB 2.0 CONNECTOR
- 1
- 1
- CO-LAYOUT
- 2
- J28 and J47
- 2
- 3
- 3
- 4
- 4
- 5
- 5
- NVIDIA CORPORATION
- 2701 SAN TOMAS
  EXPRESSWAY
- ASSEMBLY
- <ASSEMBLY_DESCRIPTION>
- SANTA CLARA, CA 95050, USA
- PAGE DETAIL
- USB2.0
  micro
- NV_PN
- 600-13449-BASE-400
- ALL NVIDIA DESIGN SPECIFICATIONS, REFERENCE SPECIFICATIONS, REFERENCE BOARDS, FILES, DRAWINGS, DIAGNOSTICS, LISTS AND OTHER DOCUMENTS OR INFORMATION (TOGETHER AND SEPARATELY, 'MATERIALS') ARE BEING PROVIDED 'AS IS'. THE MATERIALS
  MAY
- CONTAIN KNOWN AND UNKNOWN VIOLATIONS OR DEVIATIONS OF INDUSTRY STANDARDS AND SPECIFICATIONS. NVIDIA MAKES NO WARRANTIES, EXPRESSED, IMPLIED, STATUTORY OR OTHERWISE WITH RESPECT TO THE MATERIALS OR OTHERWISE, AND EXPRESSLY DISCLAIMS
  ALL
- PCB REV
- P3449-B01
- PAGE
- 7 OF 23
- .
- IMPLIED WARRANTIES INCLUDING, WITHOUT LIMITATION, THE WARRANTIES OF DESIGN, OF NONINFRINGEMENT, MERCHANTABILITY OR FITNESS FOR A PARTICULAR PURPOSE, OR ARISING FROM A COURSE OF DEALING, TRADE USAGE, TRADE PRACTICE, OR INDUSTRY
  STANDARDS.
- BOM REV
- M
- DATE
- 08-OCT-2022
- A
- B
- C
- D
- E
- F
- G
- H
sheet 17
- A
- B
- C
- D
- E
- F
- G
- H
- HDMI, DP, DSI, USBSS and PCIe
- 1
- 1
- PUT TESTPOINT
- ON BOTTOM OF
- PCB
- M.2 WIFI
- 2
- 2
- DP Con
- LOOP BACK
- 3
- 3
- HDMI Con
- USB Type-A Con (USBSS)
- 4
- 4
- 5
- 5
- NVIDIA CORPORATION
- 2701 SAN TOMAS
  EXPRESSWAY
- ASSEMBLY
- <ASSEMBLY_DESCRIPTION>
- SANTA CLARA, CA 95050, USA
- PAGE DETAIL
- SODIMM connector 3/3
- NV_PN
- 600-13449-BASE-400
- ALL NVIDIA DESIGN SPECIFICATIONS, REFERENCE SPECIFICATIONS, REFERENCE BOARDS, FILES, DRAWINGS, DIAGNOSTICS, LISTS AND OTHER DOCUMENTS OR INFORMATION (TOGETHER AND SEPARATELY, 'MATERIALS') ARE BEING PROVIDED 'AS IS'. THE MATERIALS
  MAY
- CONTAIN KNOWN AND UNKNOWN VIOLATIONS OR DEVIATIONS OF INDUSTRY STANDARDS AND SPECIFICATIONS. NVIDIA MAKES NO WARRANTIES, EXPRESSED, IMPLIED, STATUTORY OR OTHERWISE WITH RESPECT TO THE MATERIALS OR OTHERWISE, AND EXPRESSLY DISCLAIMS
  ALL
- PCB REV
- P3449-B01
- PAGE
- 6 OF 23
- IMPLIED WARRANTIES INCLUDING, WITHOUT LIMITATION, THE WARRANTIES OF DESIGN, OF NONINFRINGEMENT, MERCHANTABILITY OR FITNESS FOR A PARTICULAR PURPOSE, OR ARISING FROM A COURSE OF DEALING, TRADE USAGE, TRADE PRACTICE, OR INDUSTRY
  STANDARDS.
- BOM REV
- M
- DATE
- 08-OCT-2022
- A
- B
- C
- D
- E
- F
- G
- H
